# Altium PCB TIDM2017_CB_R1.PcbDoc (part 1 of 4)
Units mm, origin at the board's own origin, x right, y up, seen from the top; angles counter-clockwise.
Board outline 120 x 77 mm, 4 copper layers (Top Layer, Layer 1, Layer 2, Bottom Layer), stack 1.856 mm thick; 246 components, 167 nets, 1255 pads, 326 vias.
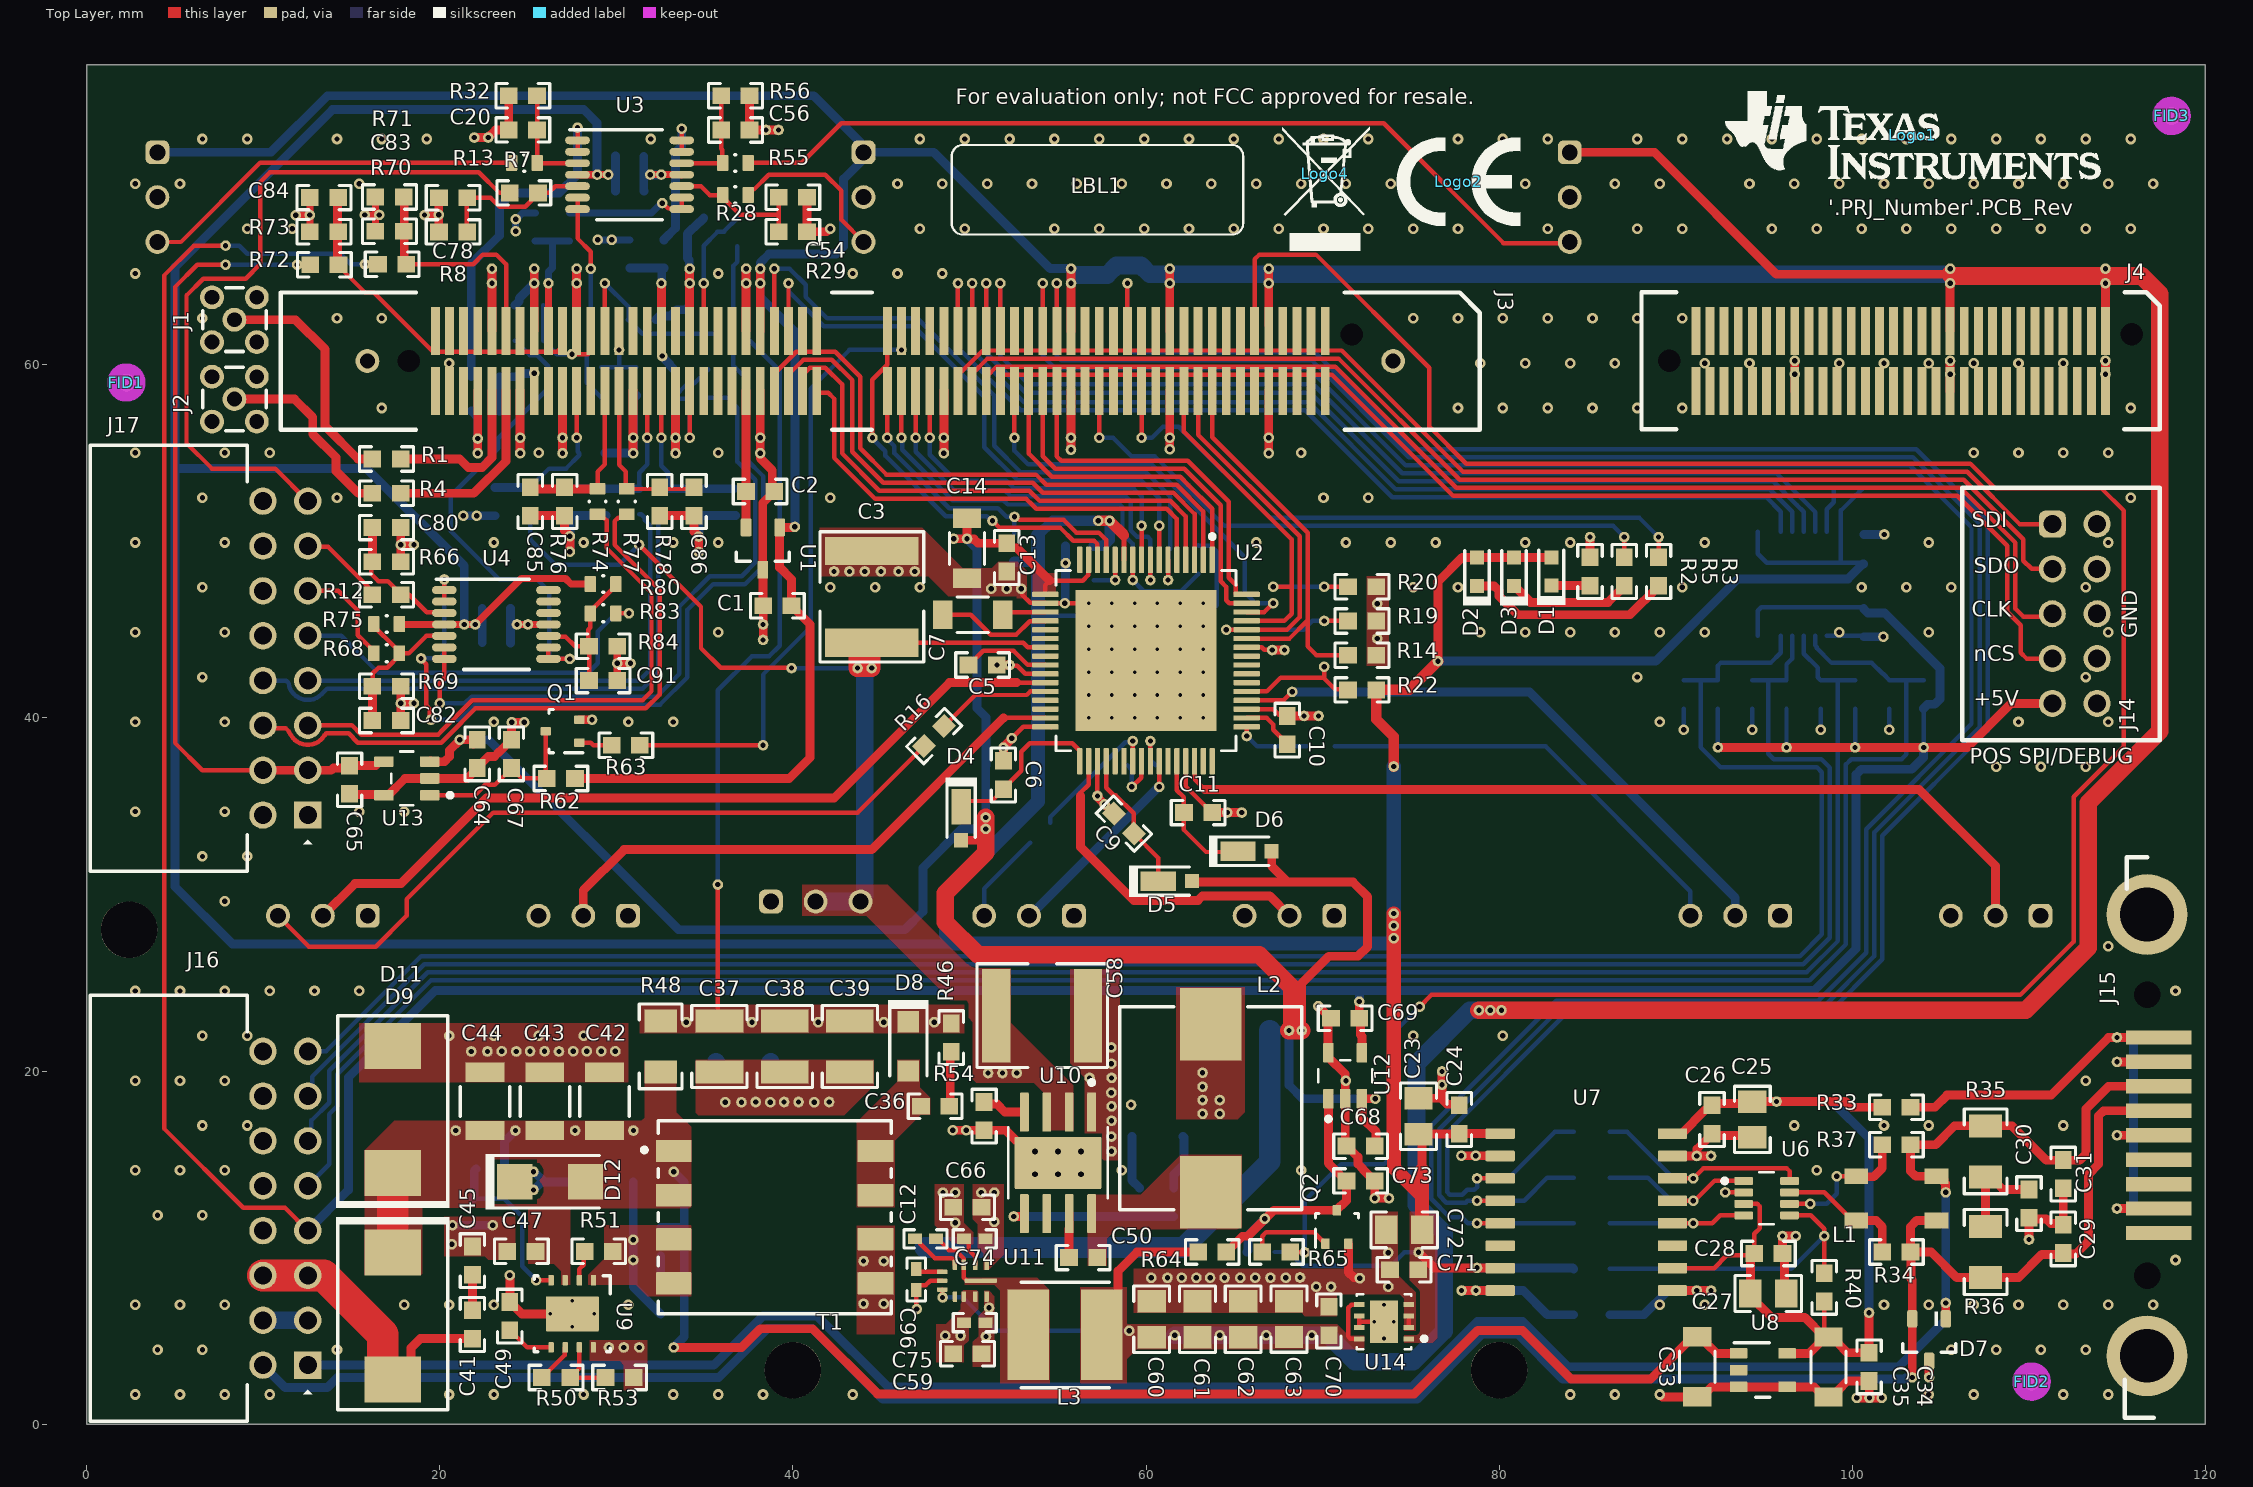
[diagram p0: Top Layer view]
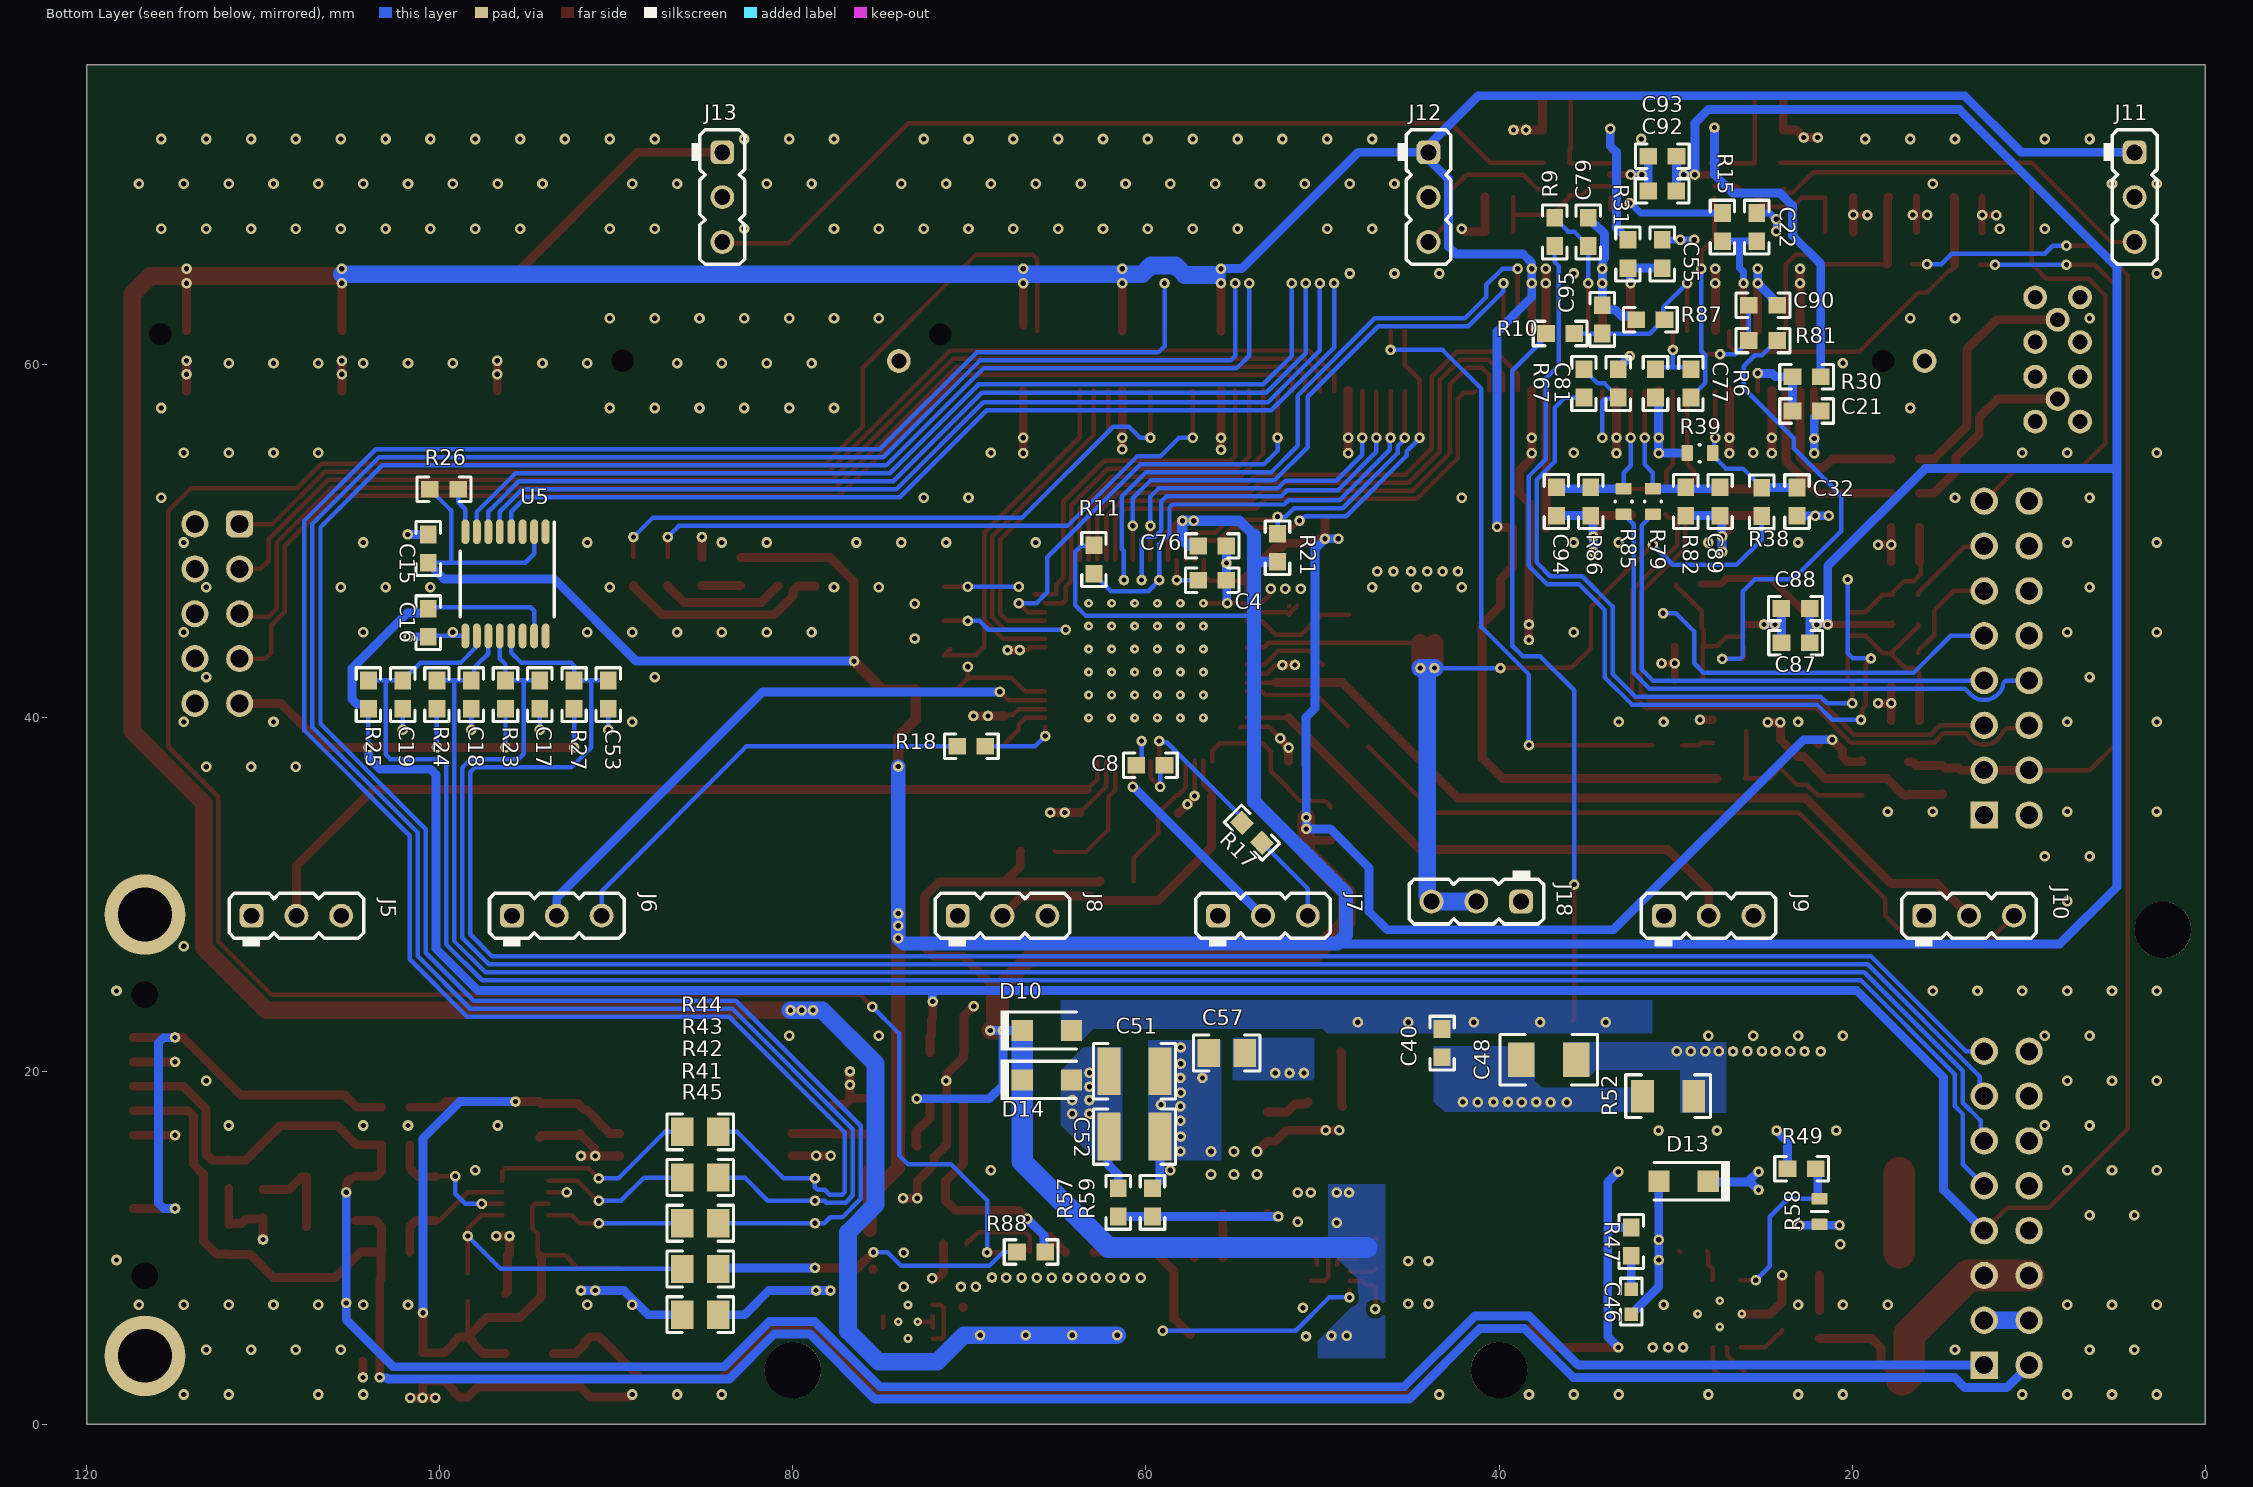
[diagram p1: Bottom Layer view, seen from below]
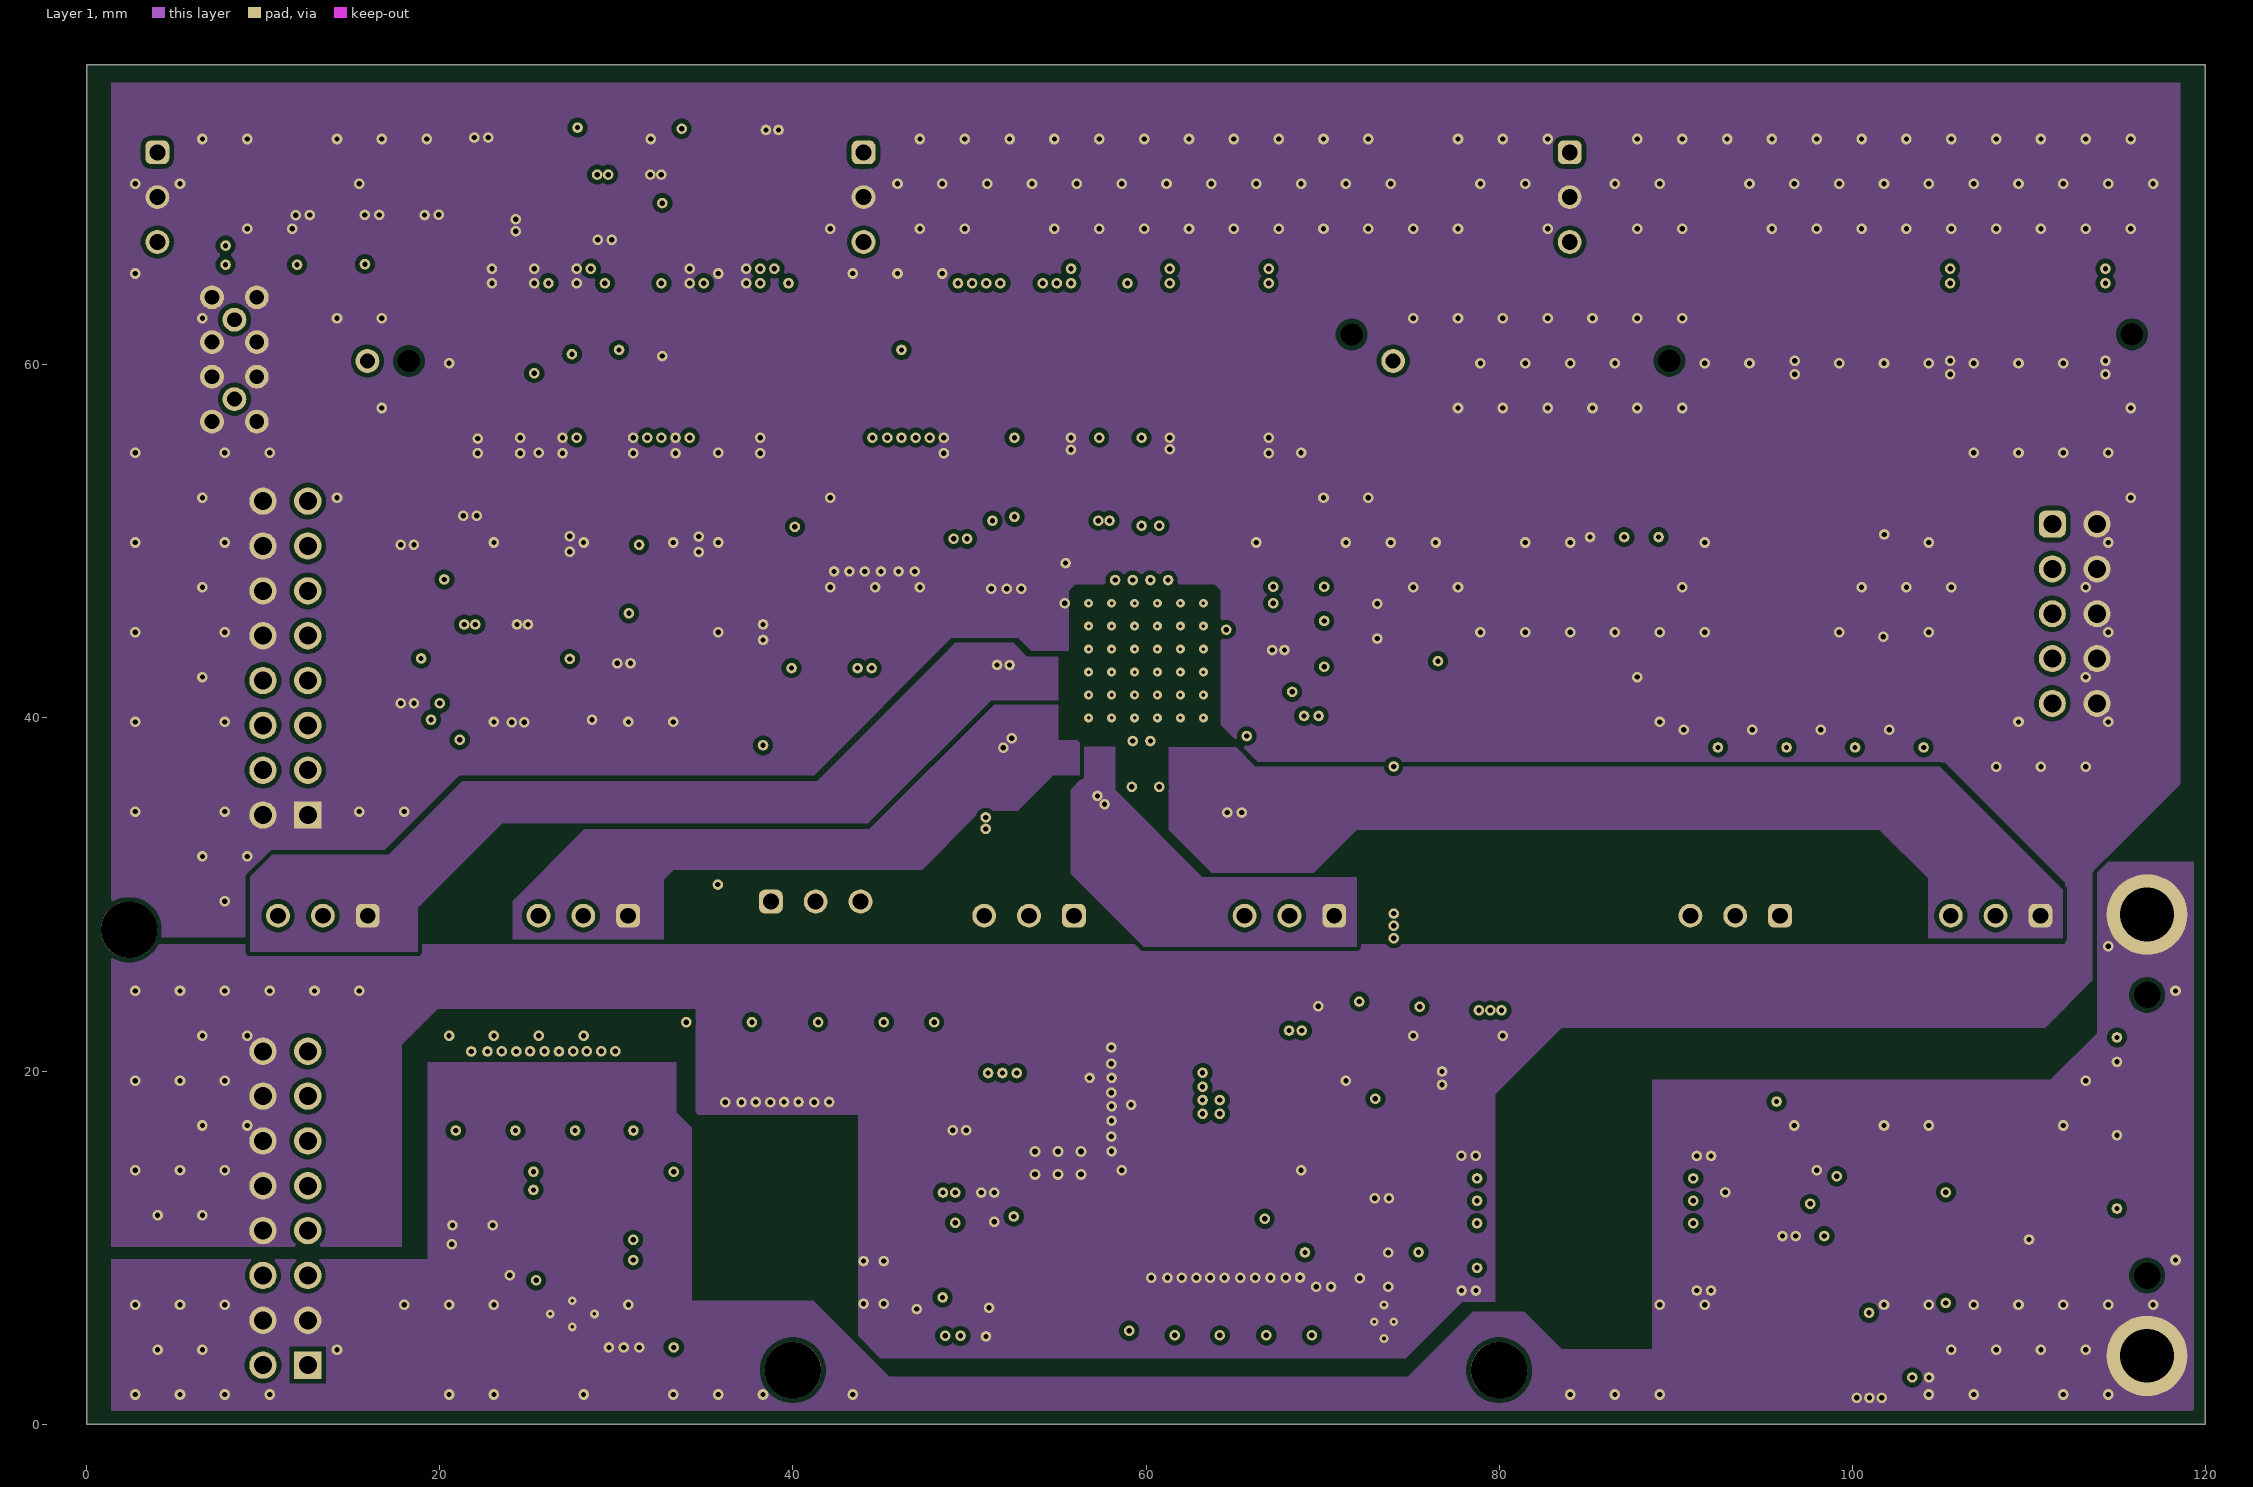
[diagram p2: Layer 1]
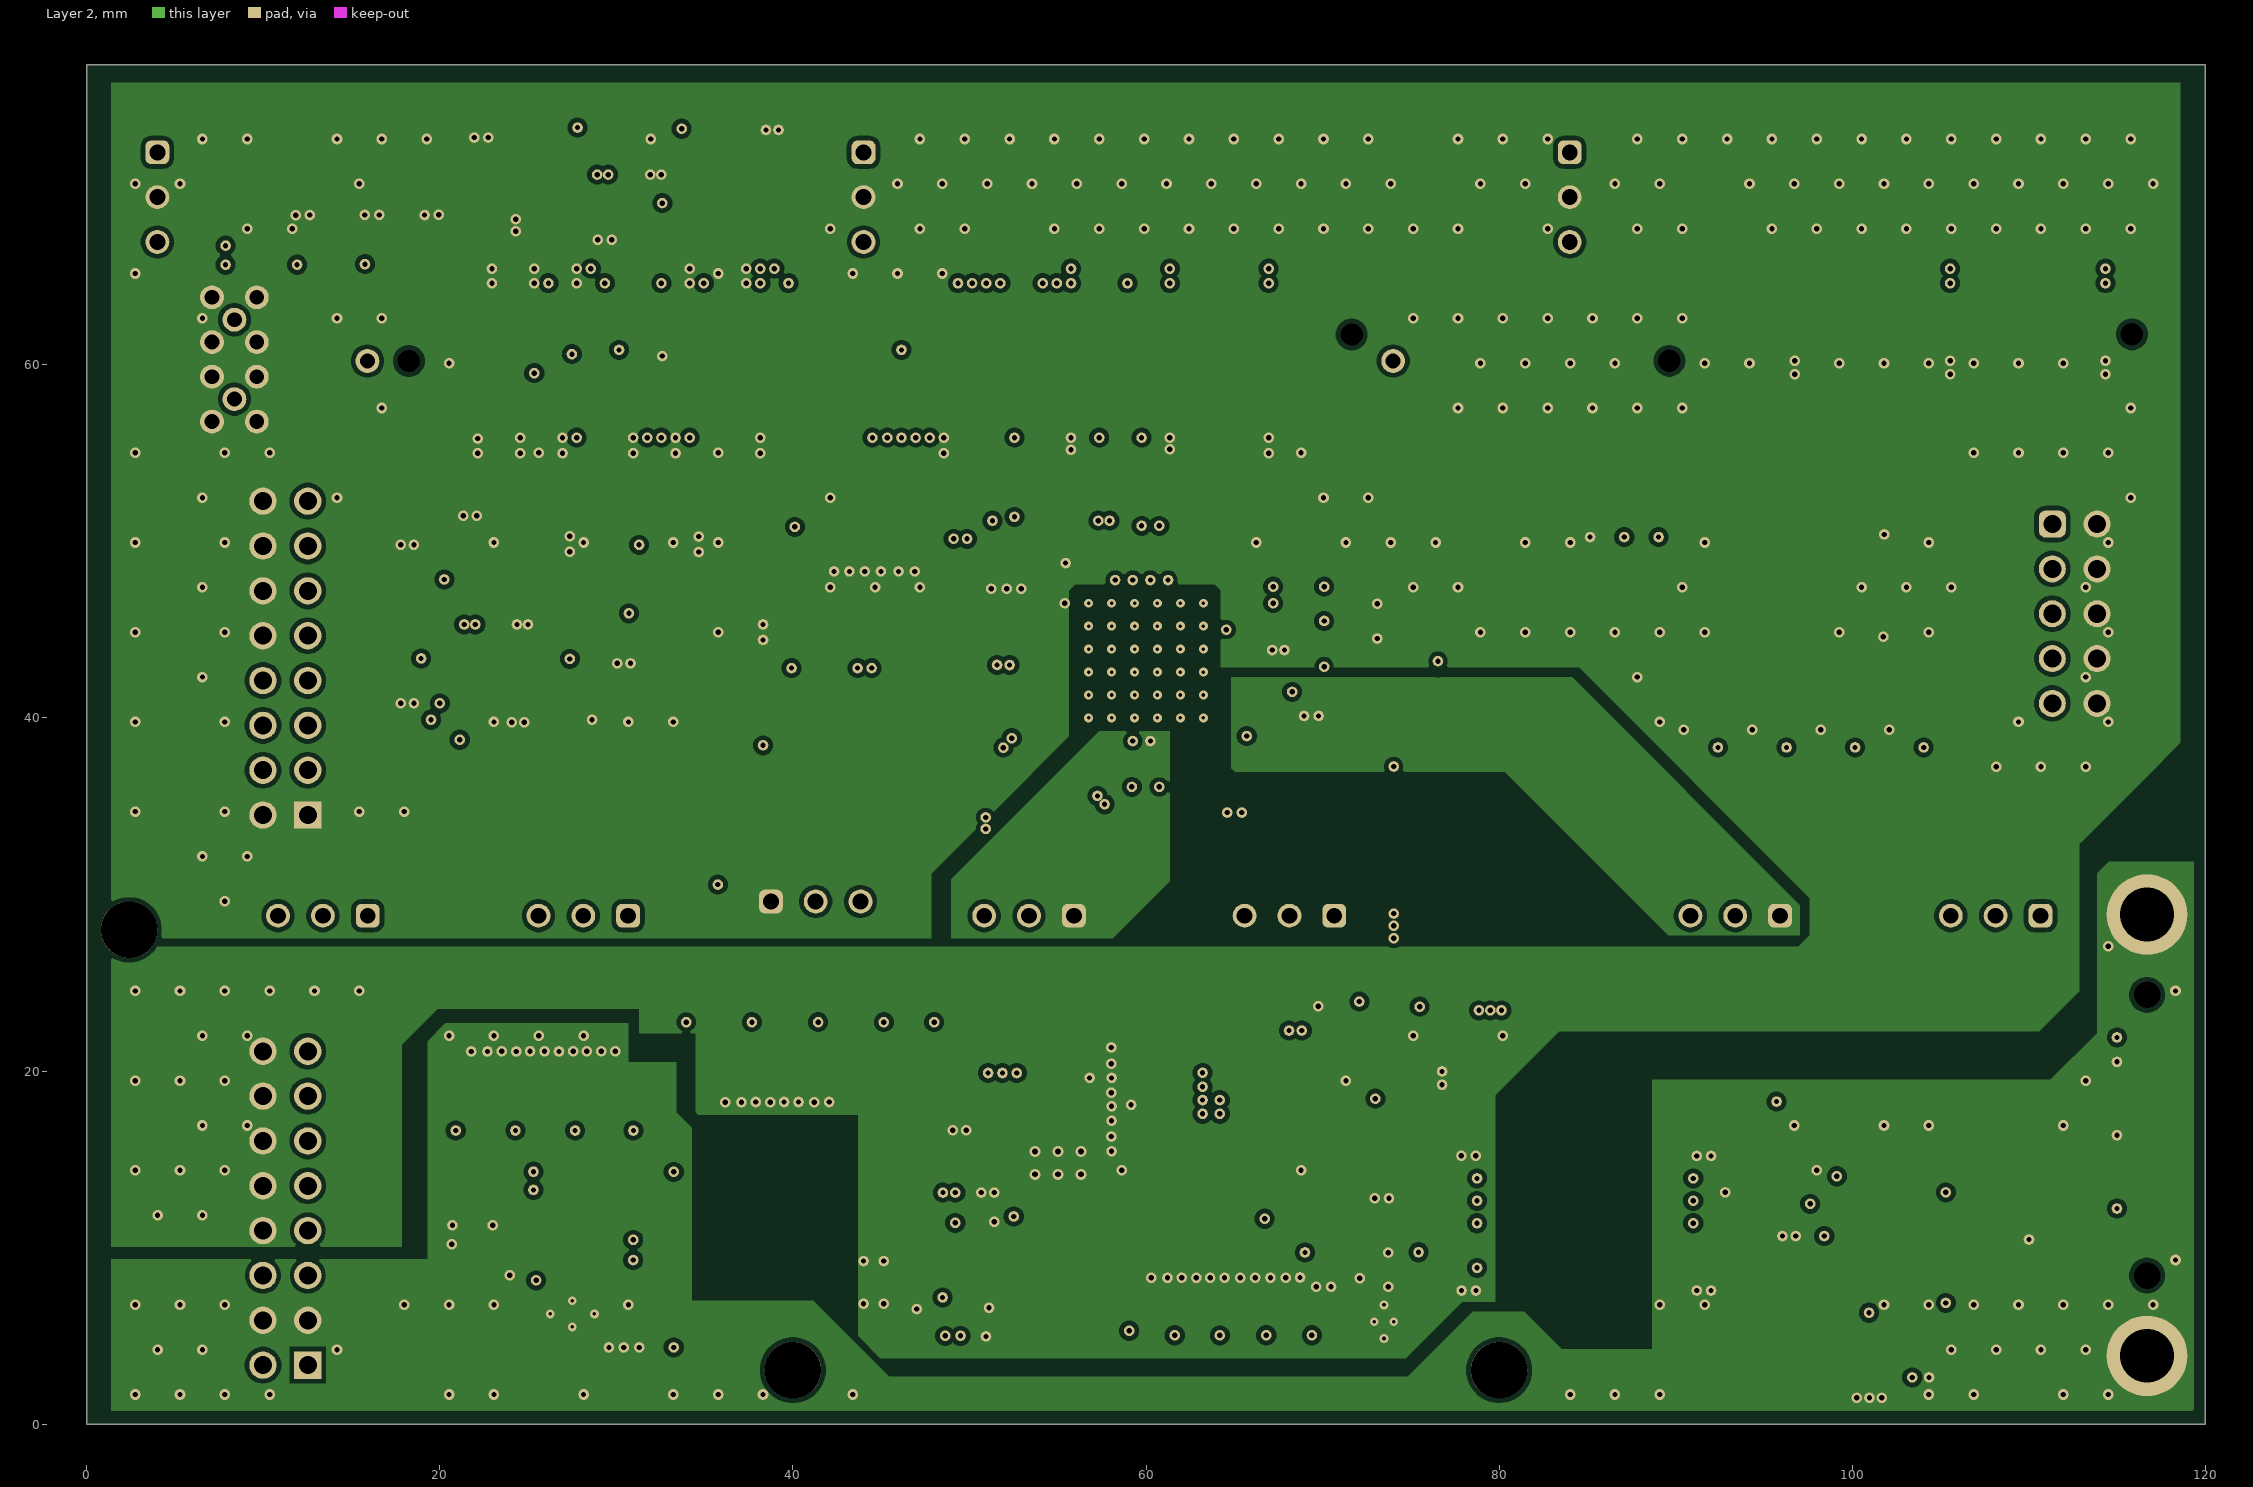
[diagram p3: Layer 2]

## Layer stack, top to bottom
Top Solder: solder mask 0.0102, Solder Resist, Dk 3.5
Top Layer: signal copper 0.07
Dielectric 1: prepreg 0.0711, PP-006, Dk 4.1
Layer 1: signal copper 0.035
Dielectric1: core 1.5037, FR-4 High Tg, Dk 4.8
Layer 2: signal copper 0.035
Dielectric 2: prepreg 0.0711, PP-006, Dk 4.1
Bottom Layer: signal copper 0.07
Bottom Solder: solder mask 0.0102, Solder Resist, Dk 3.5

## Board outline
0,0 0,77 120,77 120,0

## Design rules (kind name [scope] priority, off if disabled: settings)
AcuteAngle [All] p1: minimum=4.50000000000000E+0001 checktracksonly=FALSE
AssemblyTestPointUsage [All] p1: valid=2
BoardOutlineClearance BoardOutlineClearance_MountingHoles [OnCopper and InComponentClass('Mounting Holes')] p1: gap=1 ignorepadtopadclearanceinfootprint=FALSE
BoardOutlineClearance BoardOutlineClearance_Poly [OnCopper and IsPoly] p2: gap=0.635 ignorepadtopadclearanceinfootprint=FALSE
BoardOutlineClearance [OnCopper and Not InComponentClass('Logo') and not InComponentClass('FiducialMark') and not InRegion(1000,500,4000,800) and not InPoly] p3: gap=1.016 ignorepadtopadclearanceinfootprint=FALSE
Clearance Clearance_Keepouts [((IsTrack Or IsArc) And Not InPoly) And IsFree and IsKeepOut vs ((IsTrack Or IsArc) And Not InPoly) And IsFree and IsKeepOut] p1: gap=0 ignorepadtopadclearanceinfootprint=FALSE
Clearance Clearance_Poly [InPolygon] p2: gap=0.254 ignorepadtopadclearanceinfootprint=TRUE
Clearance Clearance_FiducialMark [IsKeepOut and InComponentClass('FiducialMark') vs IsPad and InComponentClass('FiducialMark')] p3: gap=0 ignorepadtopadclearanceinfootprint=FALSE
Clearance [All] p4: gap=0.2 ignorepadtopadclearanceinfootprint=TRUE
ComponentClearance ComponentClearance_MountingHoles_FiducialMarks [InComponentClass('Mounting Holes') vs InComponentClass('FiducialMark')] p1: gap=1.27 collisioncheckmode=3 verticalgap=0.254 showdistances=FALSE
ComponentClearance ComponentClearance_Shunt [InComponentClass('Header') vs InComponentClass('Shunt')] p2: gap=0 collisioncheckmode=3 verticalgap=0 showdistances=FALSE
ComponentClearance ComponentClearance_Logo [InComponentClass('Logo')] p3: gap=0.762 collisioncheckmode=3 verticalgap=0.254 showdistances=FALSE
ComponentClearance ComponentClearance_ScrewToNut [(HasFootprint('NY PMS 440 0025 PH')) vs (HasFootprint('Keystone_1902C'))] p4: gap=0.127 collisioncheckmode=3 verticalgap=0.254 showdistances=FALSE
ComponentClearance ComponentClearance_MountingHoles [InComponentClass('Mounting Holes')] p5: gap=2.54 collisioncheckmode=3 verticalgap=2540 showdistances=FALSE
ComponentClearance ComponentClearance_SmallPassives [HasFootprint('0201*') or HasFootprint('0402*') or HasFootprint('0508') or HasFootprint('0603*') or HasFootprint('0612') or HasFootprint('0805*') or HasFootprint('0815*') or HasFootprint('0830*') or HasFootprint('1206*') or HasFootprint('1210*') or HasFootprint('1808*') or HasFootprint('1812*') or HasFootprint('1825*') or HasFootprint('2010*') or HasFootprint('2220*') or HasFootprint('2225*') or HasFootprint('2512*') or HasFootprint('2728*') or HasFootprint('3518*') vs HasFootprint('0201*') or HasFootprint('0402*') or HasFootprint('0508') or HasFootprint('0603*') or HasFootprint('0612') or HasFootprint('0805*') or HasFootprint('0815*') or HasFootprint('0830*') or HasFootprint('1206*') or HasFootprint('1210*') or HasFootprint('1808*') or HasFootprint('1812*') or HasFootprint('1825*') or HasFootprint('2010*') or HasFootprint('2220*') or HasFootprint('2225*') or HasFootprint('2512*') or HasFootprint('2728*') or HasFootprint('3518*')] p6: gap=0.38 collisioncheckmode=3 verticalgap=0.254 showdistances=FALSE
ComponentClearance ComponentClearance_THtoSMT [IsThruComponent vs IsSMTComponent] p7: gap=0.762 collisioncheckmode=3 verticalgap=0.762 showdistances=FALSE
ComponentClearance ComponentClearance_THtoTH [IsThruComponent vs IsThruComponent] p8: gap=0.508 collisioncheckmode=3 verticalgap=0.762 showdistances=FALSE
ComponentClearance [All] p9: gap=0.508 collisioncheckmode=3 verticalgap=0.254 showdistances=FALSE
DiffPairsRouting [All] p1: maxlimit=2.54 minlimit=0.254 mostfreqgap=0.254 toplayer_minwidth=0.381 toplayer_maxwidth=0.381 toplayer_prefwidth=0.381 midlayer1_minwidth=0.381 midlayer1_maxwidth=0.381 midlayer1_prefwidth=0.381 midlayer2_minwidth=0.381 midlayer2_maxwidth=0.381 midlayer2_prefwidth=0.381 bottomlayer_minwidth=0.381 bottomlayer_maxwidth=0.381 bottomlayer_prefwidth=0.381 maxuncoupledlength=25.4
FabricationTestPointUsage TestPointUsage [All] p1: valid=2 allowmultiple=FALSE
FabricationTestpoint Testpoint [All] p1: side=3 testpointundercomponent=TRUE minsize=1.016 maxsize=2.54 preferedsize=1.524 minholesize=0 maxholesize=1.016 preferedholesize=0.813 testpointgrid=0.025 allowsidetop=TRUE allowsidebottom=TRUE usegrid=TRUE gridtolerance=0
FanoutControl Fanout_LCC [IsLCC] p1: bgadir=Out bgaviamode=Centered fanoutstyle=Auto fanoutdirection=Alternating viagrid=0.025 // Fanout_LCC (Default Rule)
FanoutControl Fanout_BGA [IsBGA] p2: bgadir=Out bgaviamode=Centered fanoutstyle=Auto fanoutdirection=Alternating viagrid=0.025 // Fanout_BGA (Default Rule)
FanoutControl Fanout_Default [All] p4: bgadir=Out bgaviamode=Centered fanoutstyle=Auto fanoutdirection=Alternating viagrid=0.025 // Fanout_Default (Default Rule)
FanoutControl Fanout_Small [(CompPinCount < 5)] p5: bgadir=Out bgaviamode=Centered fanoutstyle=Auto fanoutdirection=OutThenIn viagrid=0.025 // Fanout_Small (Default Rule)
HoleSize [All] p1: absolutevalues=TRUE maxlimit=6.375 minlimit=0.2 maxpercent=80.000 minpercent=20.000
MinimumAnnularRing MinimumAnnularRing_ThermalPadVias [IsVia and InAnyComponent] p1: minimumring=0.15
MinimumAnnularRing [All] p2: minimumring=0.2
MinimumSolderMaskSliver MinimumSolderMaskSliver_Logo [InComponentClass('Logo') vs InComponentClass('Logo')] p1: minsoldermaskwidth=0.018
MinimumSolderMaskSliver [All] p2: minsoldermaskwidth=0.1
PlaneConnect [All] p1: planeconnectstyle=Relief reliefexpansion=0.254 reliefentries=4 reliefconductorwidth=0.254 reliefairgap=0.254
PolygonConnect [All] p1: connectstyle=Direct reliefconductorwidth=0.254 reliefentries=4 polygonreliefangle="90 Angle" airgapwidth=0.254
RoutingLayers [All] p1: top layer_v5=TRUE mid layer 1_v5=FALSE mid layer 2_v5=FALSE bottom layer_v5=TRUE
RoutingVias ThermalPadVias [IsVia and InAnyComponent] p1: holewidth=0.2 width=0.5 viastyle="Through Hole" minholewidth=0.2 minwidth=0.5 maxholewidth=0.33 maxwidth=0.6
RoutingVias [All] p2: holewidth=0.406 width=0.864 viastyle="Through Hole" minholewidth=0.2 minwidth=0.61 maxholewidth=1.016 maxwidth=1.651
SilkToBoardRegionClearance [Not ((IsComment or IsDesignator) And (Hide <> 'False')) and not InRegion(1000,500,4000,800)] p1:
SilkToSilkClearance SilkToSilkClearance_Pb-FreeLogo [(HasFootprint('Pb-Free_Overlay_Medium') OR HasFootprint('Pb-Free_Overlay_Small')) vs (HasFootprint('Pb-Free_Overlay_Medium') OR HasFootprint('Pb-Free_Overlay_Small'))] p1: silktosilkclearance=0
SilkToSilkClearance [All] p2: silktosilkclearance=0.1
SilkToSolderMaskClearance SilkToComponentPadClearance [(IsPad or IsFill or IsRegion) and InAnycomponent] p1: minsilkscreentomaskgap=0.127 clearancetoexposedcopper=TRUE
SilkToSolderMaskClearance "Silk to Solder Mask Opening" [All] p2: minsilkscreentomaskgap=0.1 clearancetoexposedcopper=FALSE
SolderMaskExpansion [All] p1: expansion=0.05 istentingtop=FALSE
UnRoutedNet [All] p1: checkbadconnections=TRUE
Width [All] p1: maxlimit=2.54 minlimit=0.152 preferedwidth=0.254 checkconnectedcopper=TRUE
13 further rules are at their usual default settings.

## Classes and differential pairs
component class Header: J14
component class TIDM2017_CB_R1: J16 J17
component class Logo: Logo1
component class Label: LBL1
component class FiducialMark: FID1 FID2 FID3
component class AssemblyNote: ZZ1 ZZ2 ZZ3 ZZ4
component class Designator: C15 C16 C17 C18 C19 C53 R23 R24 R25 R26 R27 U5
component class Designator: C20 C21 C22 C54 C55 C56 C77 C78 C79 C80 C81 C82 C83 C84 C85 C86 C87 C88 C89 C90 C91 C92 C93 C94 C95 J11 J12 J13 R6 R7 R8 R9 R10 R12 R13 R15 R28 R29 R30 R31 R32 R55 R56 R66 R67 R68 R69 R70 R71 R72 R73 R74 R75 R76 R77 R78 R79 R80 R81 R82 R83 R84 R85 R86 R87 U3 U4
component class Designator: C3 C4 C5 C6 C7 C8 C9 C10 C11 C13 C14 C32 C76 D4 D5 D6 J5 J6 J7 J8 J9 J10 J18 R14 R16 R17 R18 R19 R20 R21 R22 R38 R39 U2
component class C2000_Control_Card: C1 C2 D1 D2 D3 J1 J2 J3 J4 J14 R1 R2 R3 R4 R5 R11 U1

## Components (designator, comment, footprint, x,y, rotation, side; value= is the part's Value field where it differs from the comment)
C1 "CGA3E2X7R1H104K080AA" 0603 39.122,46.351 r180 top value=0.1uF
C2 "CGA3E2X7R1H104K080AA" 0603 38.141,52.829 r180 top value=0.1uF
C3 "CGA9N2X7R2A475M230KA" 2220_250 44.469,46.854 r270 top value=4.7uF
C4 "CGA3E3X7R1H474M080AE" 0603 56.246,47.802 r180 bottom value=0.47uF
C5 "GRT188C81E475KE13D" 0603 50.75,43 r180 top value=4.7uF
C6 "GRT188C81E475KE13D" 0603 51.922,36.767 r270 top value=4.7uF
C7 "CGA5L2X7R2A474K160AA" 1206_180 50.182,45.839 r0 top value=0.47uF
C8 "GRT188C81E475KE13D" 0603 59.75,37.321 r180 bottom value=4.7uF
C9 "GRT188C81E475KE13D" 0603 58.75,34.016 r315 top value=4.7uF
C10 "GRT188C81E475KE13D" 0603 68.004,39.311 r270 top value=4.7uF
C11 "GRT188C81E475KE13D" 0603 62.95,34.642 r180 top value=4.7uF
C12 "CGA2B3X7R1H104M050BB" 0402 47.512,10.489 r180 top value=0.1uF
C13 "CGA3E3X8R1H104K080AE" 0603 52.106,49.092 r270 top value=0.1uF
C14 "CGA5L1X7R1H106K160AC" 1206_190 49.859,49.604 r270 top value=10uF
C15 "CGA3E2X7R1H104K080AA" 0603 100.657,49.595 r90 bottom value=0.1uF
C16 "CGA3E2X7R1H104K080AA" 0603 100.657,45.395 r90 bottom value=0.1uF
C17 "GRM1885C1H102JA01D" 0603 94.339,41.322 r270 bottom value=1000pF
C18 "GRM1885C1H102JA01D" 0603 98.222,41.322 r270 bottom value=1000pF
C19 "GRM1885C1H102JA01D" 0603 102.105,41.322 r270 bottom value=1000pF
C20 "GCM1885C1H471JA16D" 0603 24.703,73.305 r0 top value=470pF
C21 "GRM1885C1H471JA01D" 0603 22.58,57.385 r180 bottom value=470pF
C22 "GRM1885C1H471JA01D" 0603 25.405,67.804 r90 bottom value=470pF
C23 "CGA4J1X7S1C106K125AC" 0805_HV 75.432,17.444 r90 top locked value=10uF
C24 "0603YC104K4T4A" 0603 77.75,17.255 r90 top locked value=0.1uF
C25 "CGA4J1X7S1C106K125AC" 0805_HV 94.344,17.255 r270 top value=10uF
C26 "0603YC104K4T4A" 0603 92.059,17.255 r270 top value=0.1uF
C27 "CGA4J1X7S1C106K125AC" 0805_HV 95.252,7.4 r0 top value=10uF
C28 "0603YC104K4T4A" 0603 95.252,9.665 r0 top value=0.1uF
C29 "GRM1885C2A680JA01D" 0603 111.958,10.492 r90 top value=68pF
C30 "GCM188R71H472KA37D" 0603 110.016,12.488 r90 top value=4700pF
C31 "GRM1885C2A680JA01D" 0603 111.958,14.161 r90 top value=68pF
C32 "CGA3E3X8R1H104K080AE" 0603 23.125,52.25 r90 bottom value=0.1uF
C33 "CGA5L1X7R1H106K160AC" 1206_190 91.224,3.245 r270 top value=10uF
C34 "CGA3E3X8R1H104K080AE" 0603 100.955,3.245 r270 top value=0.1uF
C35 "CGA5L1X7R1H106K160AC" 1206_190 98.66,3.236 r270 top value=10uF
C36 "GRM1885C2A220JA01D" 0603 48.053,18 r180 top locked value=22pF
C37 "TMK325B7226KMHP" 1210_270 35.841,21.394 r270 top locked value=22uF
C38 "TMK325B7226KMHP" 1210_270 39.535,21.394 r270 top locked value=22uF
C39 "TMK325B7226KMHP" 1210_270 43.228,21.394 r270 top locked value=22uF
C40 "C0603C104K5RACAUTO" 0603 43.228,21.584 r270 bottom value=0.1uF
C41 "CGA3E2X7R1H473K080AA" 0603 21.847,5.644 r90 top locked value=0.047uF
C42 "CGA6P3X7S1H106K250AB" 1210_280 29.326,18.281 r270 top locked value=10uF
C43 "CGA6P3X7S1H106K250AB" 1210_280 25.946,18.281 r270 top locked value=10uF
C44 "CGA6P3X7S1H106K250AB" 1210_280 22.566,18.281 r270 top locked value=10uF
C45 "CGA3E2X7R1H473K080AA" 0603 21.847,9.261 r90 top locked value=0.047uF
C46 "GRM1885C2A220JA01D" 0603_HV 32.511,6.939 r270 bottom value=22pF
C47 "C0603C104K5RACTU" 0603 24.619,9.786 r180 top locked value=0.1uF
C48 "202R18W102KV4E" 1206_190M 37.191,20.643 r180 bottom value=1000pF
C49 "GCM188R71E473KA37D" 0603 23.966,6.119 r90 top locked value=0.047uF
C50 "C0603C104K5RACAUTO" 0603 56.436,9.434 r0 top locked value=0.1uF
C51 "TMK325B7226KMHP" 1210_270 60.65,19.984 r180 bottom locked value=22uF
C52 "TMK325B7226KMHP" 1210_270 60.65,16.29 r180 bottom value=22uF
C53 "GRM1885C1H102JA01D" 0603 90.456,41.322 r270 bottom value=1000pF
C54 "GCM1885C1H471JA16D" 0603 39.997,69.5 r180 top value=470pF
C55 "GRM1885C1H471JA01D" 0603 30.76,66.281 r90 bottom value=470pF
C56 "GCM1885C1H471JA16D" 0603 36.744,73.305 r180 top value=470pF
C57 "GCM21BR72A104KA37L" 0805_HV 55.425,21.019 r0 bottom locked value=0.1uF
C58 "CGA9N2X7R2A475M230KA" 2220_250 54.119,23.135 r0 top locked value=4.7uF
C59 "GRT188C81C106ME13D" 0603 49.886,3.982 r0 top value=10uF
C60 "GRT21BR61E226ME13L" 0805_HV 60.324,5.939 r90 top locked value=22uF
C61 "GRT21BR61E226ME13L" 0805_HV 62.914,5.939 r90 top locked value=22uF
C62 "GRT21BR61E226ME13L" 0805_HV 65.504,5.939 r90 top locked value=22uF
C63 "GRT21BR61E226ME13L" 0805_HV 68.094,5.949 r90 top locked value=22uF
C64 "GCM188R71C105KA64J" 0603 22.115,37.967 r270 top value=1uF
C65 "GRM188R71A225KE15J" 0603 14.887,36.5 r270 top value=2.2uF
C66 "GRT188C81C106ME13D" 0603 49.886,12.283 r0 top value=10uF
C67 "C0603C104K5RACAUTO" 0603 24.056,37.967 r270 top value=0.1uF
C68 "GCM188R71C105KA64J" 0603 72.157,15.747 r180 top locked value=1uF
C69 "GRM188R71A225KE15J" 0603 71.282,22.985 r180 top locked value=2.2uF
C70 "GRM188R71A225KE15J" 0603 70.361,5.84 r90 top locked value=2.2uF
C71 "GRM188R71A225KE15J" 0603 74.624,8.744 r180 top locked value=2.2uF
C72 "GRT21BR61E226ME13L" 0805_HV 74.624,11.008 r180 top locked value=22uF
C73 "C0603C104K5RACAUTO" 0603 72.157,13.777 r180 top locked value=0.1uF
C74 "GCM155R71C224KE02D" 0402 50.299,10.489 r0 top value=0.22uF
C75 "GCM155R71C224KE02D" 0402 50.299,5.754 r0 top value=0.22uF
C76 "CGA3E3X8R1H104K080AE" 0603 56.246,49.744 r180 bottom value=0.1uF
C77 "GRM1885C1H471JA01D" 0603 31.139,58.948 r270 bottom value=470pF
C78 "GCM1885C1H471JA16D" 0603 20.752,69.472 r0 top value=470pF
C79 "GRM1885C1H471JA01D" 0603 34.95,67.53 r90 bottom value=470pF
C80 "GCM1885C1H471JA16D" 0603 16.982,50.785 r180 top value=470pF
C81 "GRM1885C1H471JA01D" 0603 33.253,58.948 r90 bottom value=470pF
C82 "GCM1885C1H471JA16D" 0603 16.982,39.858 r180 top value=470pF
C83 "GCM1885C1H471JA16D" 0603 17.147,67.568 r0 top value=470pF
C84 "GCM1885C1H471JA16D" 0603 13.438,69.476 r0 top value=470pF
C85 "GCM1885C1H471JA16D" 0603 25.128,52.26 r90 top value=470pF
C86 "GCM1885C1H471JA16D" 0603 34.397,52.26 r90 top value=470pF
C87 "GRT188C81E475KE13D" 0603 23.205,44.254 r180 bottom value=4.7uF
C88 "CGA3E3X8R1H104K080AE" 0603 23.21,46.197 r0 bottom value=0.1uF
C89 "GCM1885C1H471JA16D" 0603 27.481,52.26 r90 bottom value=470pF
C90 "GRM1885C1H471JA01D" 0603 25.053,63.375 r180 bottom value=470pF
C91 "GCM1885C1H471JA16D" 0603 29.25,42.12 r180 top value=470pF
C92 "GRT188C81E475KE13D" 0603 30.76,69.854 r180 bottom value=4.7uF
C93 "CGA3E3X8R1H104K080AE" 0603 30.749,71.823 r0 bottom value=0.1uF
C94 "GCM1885C1H471JA16D" 0603 36.75,52.26 r90 bottom value=470pF
C95 "GCM1885C1H471JA16D" 0603 34.15,62.575 r270 bottom locked value=470pF
C96 "GRT155R6YA105KE13D" 0402 46.984,8.188 r270 top value=1uF
D1 "150060GS75000" WL-SMCW_GREEN 82.959,48.295 r90 top value=Green
D2 "150060RS75000" WL-SMCW_RED 78.742,48.281 r90 top value=Red
D3 "150060GS75000" WL-SMCW_GREEN 80.851,48.281 r90 top value=Green
D4 "PD3S220L-7" PowerDI323 49.527,34.321 r270 top value=20V
D5 "PD3S220L-7" PowerDI323 61.349,30.76 r0 top value=20V
D6 "PD3S220L-7" PowerDI323 65.857,32.45 r0 top value=20V
D7 "CDSOT23-SM712" SOT-23 104.355,4.764 r270 top value=7V
D8 "PMEG60T30ELRX" SOD-123W 46.537,21.394 r270 top value=60V
D9 "SS3H10HE3_A/I" SMC_265 17.332,6.119 r270 top locked value=100V
D10 "PMEG60T30ELRX" SOD-123W 65.614,22.294 r180 bottom locked value=60V
D11 "TPSMD26A" SMC_265 17.332,17.828 r90 top locked value=26V
D12 "3SMAJ5935B-TP" SMA 26.25,13.723 r0 top locked value=27V
D13 "PMEG60T30ELRX" SOD-123W 29.55,13.758 r0 bottom value=60V
D14 "PMEG60T30ELRX" SOD-123W 65.614,19.5 r180 bottom value=60V
FID1 "Fiducial" Fiducial10-20 2.25,59 r0 top
FID2 "Fiducial" Fiducial10-20 110.161,2.411 r0 top
FID3 "Fiducial" Fiducial10-20 118.094,74.1 r0 top
J1 "0734151471" Molex_0734151471 8.364,62.557 r0 top
J2 "0734151471" Molex_0734151471 8.364,58.058 r0 top
J3 "HSEC8-160-01-L-DV-A-BL" controlCARD-120HSEC 43.107,60.197 r0 top locked
J4 "HSEC8-130-01-L-DV-A" controlCARD-180HSEC-60pinAddon 102.748,60.228 r0 top locked
J5 "801-41-003-10-001000" Mill-Max_801-41-003-10-001000 108.126,28.798 r180 bottom locked
J6 "801-41-003-10-001000" Mill-Max_801-41-003-10-001000 93.376,28.798 r180 bottom locked
J7 "801-41-003-10-001000" Mill-Max_801-41-003-10-001000 53.376,28.798 r180 bottom locked
J8 "801-41-003-10-001000" Mill-Max_801-41-003-10-001000 68.126,28.798 r180 bottom locked
J9 "801-41-003-10-001000" Mill-Max_801-41-003-10-001000 28.126,28.798 r180 bottom locked
J10 "801-41-003-10-001000" Mill-Max_801-41-003-10-001000 13.376,28.798 r180 bottom locked
J11 "801-41-003-10-001000" Mill-Max_801-41-003-10-001000 4,69.5 r270 bottom locked
J12 "801-41-003-10-001000" Mill-Max_801-41-003-10-001000 44,69.5 r270 bottom locked
J13 "801-41-003-10-001000" Mill-Max_801-41-003-10-001000 84,69.5 r270 bottom locked
J14 "TSW-105-08-G-D" Samtec_TSW-105-08-x-D 112.605,45.903 r0 top
J15 "190-009-263R001" NORCOMP_190-009-263R001 119.5,16.365 r270 top locked
J16 "TSS-108-04-L-D-RA" Samtec_TSS-108-04-x-D-RA 11.25,12.23 r180 top locked
J17 "TSS-108-04-L-D-RA" Samtec_TSS-108-04-x-D-RA 11.25,43.39 r180 top locked
J18 "801-41-003-10-001000" Mill-Max_801-41-003-10-001000 41.29,29.599 r0 bottom locked
L1 "ACT45B-510-2P-TL003" ACT45B_NoSilk 102.505,12.79 r180 top value=51uH
L2 "PA4342.683NLT" PA4342_2 63.673,17.89 r180 top locked value=68uH
L3 "SRN6045TA-100M" SRN6045TA 55.411,5.062 r0 top locked value=10uH
LBL1 "THT-14-423-10" Label_650x200 57.25,69.918 r0 top
Logo1 "Texas Instruments" TI_Stacked_Overlay_Small 103.442,73.01 r0 top
Logo2 "CE Mark" CE_Mark_5mm 77.705,70.372 r0 top
Logo3 "FCC disclaimer" FCC_disclaimer 58.25,89.223 r0 top
Logo4 "WEEE logo" WEEE_Minimum 70.15,70.826 r0 top
Q1 "BSS138WH6327XTSA1" SOT-323 26.95,39.25 r180 top locked value=60V
Q2 "BSS138WH6327XTSA1" SOT-323 70.811,11.164 r90 top locked value=60V
R1 "CRCW060347R0FKEA" 0603 16.982,54.667 r0 top value=47.0
R2 "CRCW06034K64FKEA" 0603 85.15,48.295 r270 top value=4.64k
R3 "CRCW06031K15FKEA" 0603 89.035,48.295 r270 top value=1.15k
R4 "CRCW060347R0FKEA" 0603 16.982,52.725 r0 top value=47.0
R5 "CRCW06034K64FKEA" 0603 87.091,48.295 r270 top value=4.64k
R6 "RC0603FR-0751R1L" 0603 29.13,58.948 r90 bottom value=51.1
R7 "RT0603BRD0718K4L" 0603 24.762,69.74 r0 top value=18.4k
R8 "RC0603FR-0710KL" 0603 20.752,67.53 r0 top value=10.0k
R9 "RC0603FR-0751R1L" 0603 36.844,67.53 r90 bottom value=51.1
R10 "RT0603DRE0743K7L" 0603 36.544,61.775 r180 bottom locked value=43.7k
R11 "CRCW060310K0FKEA" 0603 62.95,48.973 r90 bottom value=10.0k
R12 "RT0603BRD0718K4L" 0603 16.982,46.979 r0 top value=18.4k
R13 "ERJ-PB3B6041V" FP-ERJ-PB3B6041V_0603-MFG 24.787,71.44 r0 top
R14 "ERA-3ARW104V" 0603 72.239,43.551 r180 top value=100k
R15 "RC0603FR-0751R1L" 0603 27.349,67.804 r270 bottom value=51.1
R16 "RT0603BRD07271RL" 0603 48,38.975 r225 top value=271
R17 "RT0603BRD07271RL" 0603 54,33.5 r225 bottom value=271
R18 "RT0603BRD07271RL" 0603 69.896,38.392 r0 bottom value=271
R19 "ERA-3ARW104V" 0603 72.239,45.493 r180 top value=100k
R20 "ERA-3ARW104V" 0603 72.239,47.434 r180 top value=100k
R21 "RMCF0603FT10K0" 0603 52.55,49.642 r90 bottom value=10.0k
R22 "RMCF0603FT10K0" 0603 72.239,41.587 r180 top value=10.0k
R23 "CRCW06031K00FKEA" 0603 96.28,41.322 r270 bottom value=1.00k
R24 "CRCW06031K00FKEA" 0603 100.163,41.322 r270 bottom value=1.00k
R25 "CRCW06031K00FKEA" 0603 104.046,41.322 r270 bottom value=1.00k
R26 "CRCW06031K00FKEA" 0603 99.761,52.949 r180 bottom value=1.00k
R27 "CRCW06031K00FKEA" 0603 92.397,41.322 r270 bottom value=1.00k
R28 "ERJ-PB3B6041V" FP-ERJ-PB3B6041V_0603-MFG 36.744,69.615 r180 top locked
R29 "RC0603FR-0710KL" 0603 39.997,67.54 r180 top locked value=10.0k
R30 "RC0603FR-0751R1L" 0603 22.579,59.328 r0 bottom locked value=51.1
R31 "RC0603FR-0751R1L" 0603 32.703,66.281 r270 bottom locked value=51.1
R32 "RC0603FR-0710KL" 0603 24.703,75.246 r0 top value=10.0k
R33 "RMCF0603ZT0R00" 0603 102.505,17.948 r180 top value=0
R34 "PMR03EZPJ000" 0603 102.505,9.75 r0 top value=0
R35 "CRCW120660R0KNEAIF" 1206 107.556,9.75 r270 top value=60
R36 "CRCW120660R0KNEAIF" 1206 107.556,15.449 r270 top value=60
R37 "PMR03EZPJ000" 0603 102.505,15.829 r0 top value=0
R38 "ERA-3ARW104V" 0603 25.128,52.244 r90 bottom value=100k
R39 "ERJ-PB3B6041V" FP-ERJ-PB3B6041V_0603-MFG 28.625,55 r180 bottom
R40 "PMR03EZPJ000" 0603 98.418,7.748 r270 top value=0
R41 "CRCW08050000Z0EAHP" 0805_HV 85.25,8.788 r0 bottom locked value=0
R42 "CRCW08050000Z0EAHP" 0805_HV 85.25,11.378 r0 bottom locked value=0
R43 "CRCW08050000Z0EAHP" 0805_HV 85.25,13.968 r0 bottom locked value=0
R44 "CRCW08050000Z0EAHP" 0805_HV 85.25,16.558 r0 bottom locked value=0
R45 "CRCW08050000Z0EAHP" 0805_HV 85.25,6.198 r0 bottom locked value=0
R46 "CRCW0603100RFKEAHP" 0603 48.97,21.894 r90 top locked value=100
R47 "CRCW0603100RFKEA" 0603 32.511,10.341 r90 bottom value=100
R48 "RCA12060000ZSEA" 1206 32.505,21.394 r90 top locked value=0
R49 "CRCW0603261KFKEA" 0603 22.859,14.459 r0 bottom value=261k
R50 "CRCW0603261KFKEA" 0603 26.581,2.64 r180 top locked value=261k
R51 "CRCW0603121KFKEA" 0603 29,9.786 r0 top value=121k
R52 "RCA12060000ZSEA" 1206 30.424,18.58 r0 bottom value=0
R53 "CRCW060312K1FKEA" 0603 30.186,2.64 r180 top locked value=12.1k
R54 "CRCW060364K9FKEA" 0603 50.827,17.446 r90 top locked value=64.9k
R55 "ERJ-PB3B6041V" FP-ERJ-PB3B6041V_0603-MFG 36.744,71.44 r180 top
R56 "RC0603FR-0710KL" 0603 36.744,75.246 r180 top value=10.0k
R57 "ERA-3ARW104V" 0603 61.573,12.561 r90 bottom locked value=100k
R58 "ERJ-PB3D9762V" FP-ERJ-PB3D9762V_0603-MFG 21.847,12.044 r90 bottom value=97.6k
R59 "CRCW06039K09FKEA" 0603 59.634,12.561 r270 bottom locked value=9.09k
R62 "CRCW06031K00FKEA" 0603 26.853,36.573 r180 top value=1.00k
R63 "RMCF0603FT10K0" 0603 30.533,38.45 r180 top locked value=10.0k
R64 "CRCW06031K00FKEA" 0603 63.754,9.75 r0 top value=1.00k
R65 "RMCF0603FT10K0" 0603 67.38,9.75 r180 top value=10.0k
R66 "RC0603FR-0710KL" 0603 16.982,48.844 r180 top value=10.0k
R67 "RC0603FR-0751R1L" 0603 35.194,58.948 r90 bottom value=51.1
R68 "ERJ-PB3B6041V" FP-ERJ-PB3B6041V_0603-MFG 16.982,43.663 r0 top
R69 "RC0603FR-0710KL" 0603 16.982,41.8 r180 top value=10.0k
R70 "RT0603BRD0718K4L" 0603 17.297,65.705 r0 top value=18.4k
R71 "RC0603FR-0710KL" 0603 17.147,69.509 r0 top value=10.0k
R72 "RT0603BRD0718K4L" 0603 13.463,65.671 r0 top value=18.4k
R73 "RC0603FR-0710KL" 0603 13.438,67.535 r0 top value=10.0k
R74 "ERJ-PB3B6041V" FP-ERJ-PB3B6041V_0603-MFG 28.932,52.26 r90 top
R75 "ERJ-PB3B6041V" FP-ERJ-PB3B6041V_0603-MFG 16.982,45.321 r180 top
R76 "RC0603FR-0710KL" 0603 27.069,52.26 r90 top value=10.0k
R77 "ERJ-PB3B6041V" FP-ERJ-PB3B6041V_0603-MFG 30.591,52.26 r90 top
R78 "RC0603FR-0710KL" 0603 32.455,52.26 r90 top value=10.0k
R79 "ERJ-PB3B6041V" FP-ERJ-PB3B6041V_0603-MFG 31.287,52.26 r90 bottom
R80 "ERJ-PB3B6041V" FP-ERJ-PB3B6041V_0603-MFG 29.25,47.583 r0 top
R81 "RC0603FR-0751R1L" 0603 25.053,61.375 r0 bottom value=51.1
R82 "RC0603FR-0710KL" 0603 29.423,52.26 r90 bottom value=10.0k
R83 "ERJ-PB3B6041V" FP-ERJ-PB3B6041V_0603-MFG 29.25,45.925 r180 top
R84 "RC0603FR-0710KL" 0603 29.25,44.061 r180 top value=10.0k
R85 "ERJ-PB3B6041V" FP-ERJ-PB3B6041V_0603-MFG 32.945,52.26 r90 bottom
R86 "RC0603FR-0710KL" 0603 34.809,52.26 r90 bottom value=10.0k
R87 "RC0603FR-0710KL" 0603 31.432,62.557 r180 bottom value=10.0k
R88 "CRCW06031K00FKEA" 0603 66.505,9.75 r180 bottom value=1.00k
T1 "ZA9672-BE" FP-ZA9672-BE_SMD8-MFG 38.964,11.719 r0 top locked
U1 "REF3133AQDBZRQ1" DBZ0003A_N 38.294,49.589 r270 top
U2 "DRV3256EPAPRQ1" PAP0064N-MFG 60,43.25 r270 top
U3 "TLV9064IPWR" PW0014A_N 30.749,70.77 r0 top
U4 "TLV9064IPWR" PW0014A_N 23.205,45.294 r0 top locked
U5 "TXB0106PWR" PW0016A_N 96.28,47.595 r270 bottom
U6 "TCAN1044DDFRQ1" DDF0008A-MFG 95.151,12.802 r0 top
U7 "ISO7731DWR" DW0016B_HV 84.941,12.013 r0 top
U8 "TPS7B6950QDBVRQ1" DBV0005A_N 94.942,3.059 r0 top
U9 "LM25184QNGURQ1" NGU0008C 27.504,6.246 r270 top locked
U10 "LMR38010SQDDARQ1" DDA0008E-MFG 55.015,14.799 r270 top locked
U11 "LMR33620AQ5RNXRQ1" RNX0012B 49.852,8.121 r270 top
U12 "TPS7B4255QDBVRQ1" DBV0005A-MFG 71.282,19.735 r90 top locked
U13 "TPS7B4255QDBVRQ1" DBV0005A-MFG 18.127,36.573 r180 top
U14 "TPS7A21XXPQWDRBRQ1" DRB0008K-MFG 73.481,5.799 r180 top locked
ZZ1 "This Assembly Note is for PCB labels only" AssemblyNoteLabel 4.8,99.1 r0 top
ZZ2 "These assemblies are ESD sensitive, ESD precautions shall be observed." AssemblyNote 4.786,97.25 r0 top
ZZ3 "These assemblies must be clean and free from flux and all contaminants. Use of no clean flux is not acceptable." AssemblyNote 4.78,95.25 r0 top
ZZ4 "These assemblies must comply with workmanship standards IPC-A-610 Class 2, unless otherwise specified." AssemblyNote 4.786,93.25 r0 top

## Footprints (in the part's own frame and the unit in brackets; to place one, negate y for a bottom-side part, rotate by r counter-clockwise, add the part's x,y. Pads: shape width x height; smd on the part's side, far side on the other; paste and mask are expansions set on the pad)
0402 [mm] "0402 from SM-752 data"
  rect 0.8x0.6 smd: 1(-0.6,0) 2(0.6,0)
  silkscreen extent -1.22,-0.52 1.22,0.52, body extent -0.55,-0.3 0.55,0.3, height 0.6
0603 [mm] "0603 from SM-752 data"
  rect 1x0.95 smd: 1(-0.8,0) 2(0.8,0)
  silkscreen extent -1.52,-0.69 1.52,0.69, body extent -0.87,-0.47 0.87,0.47, height 1
0603_HV [mil] "Ernesto recommended land pattern.  26 mil between pads."
  rect 30x30 smd: 1(-28,0) 2(28,0)
  silkscreen extent -52,-24 52,24, body extent -34,-19 34,19, height 39
0805_HV [mil] "0805 with 30mil clearance between pads"
  rect 50x63 smd: 1(-40,0) 2(40,0)
  silkscreen extent -74,-40 74,40, body extent -43,-29 43,29, height 57
1206 [mm] "1206 from SM-752 data"
  rect 1.3x1.85 smd: 1(-1.45,0) 2(1.45,0)
  silkscreen extent -2.4,-1.21 2.4,1.21, body extent -1.7,-0.9 1.7,0.9, height 1.35
1206_180 [mm] "1206_180"
  rect 1.1x1.6 smd: 1(-1.7,0) 2(1.7,0)
  silkscreen extent -0.9,-1 0.9,1, body extent -1.75,-0.95 1.75,0.95, height 1.8
1206_190 [mm] "1206_190"
  rect 1.1x1.6 smd: 1(-1.7,0) 2(1.7,0)
  silkscreen extent -0.9,-1 0.9,1, body extent -1.75,-0.95 1.75,0.95, height 1.9
1206_190M [mm] "1206_190"
  rect 1.5x1.95 smd: 1(-1.55,0) 2(1.55,0)
  silkscreen extent -2.76,-1.44 2.76,1.44, body extent -1.75,-0.95 1.75,0.95, height 1.9
1210_270 [mm] "1210"
  rect 1.3x2.7 smd: 1(-1.45,0) 2(1.45,0)
  silkscreen extent -2.32,-1.57 2.32,1.57, body extent -1.7,-1.35 1.7,1.35, height 2.7
1210_280 [mm] "SMD, 2-Leads, Body 3.6x2.8mm, Height 2.8mm"
  rect 1.1x2.2 smd: 1(-1.65,0) 2(1.65,0)
  silkscreen extent -0.84,-1.4 0.84,1.4, body extent -1.8,-1.4 1.8,1.4, height 2.8
2220_250 [mm] "2220"
  rect 1.6x5.3 smd: 1(-2.6,0) 2(2.6,0)
  silkscreen extent -3.69,-2.94 3.69,2.94, body extent -2.95,-2.62 2.95,2.62, height 2.5
ACT45B_NoSilk [mm] "SMD, 4-Leads, Body 4.7 x 3.7 mm"
  rect 1.35x0.9 smd: 1(-2.275,1.25) 2(-2.275,-1.25) 3(2.275,-1.25) 4(2.275,1.25)
  body extent -2.35,-1.7 2.35,1.7, height 3
AssemblyNote [mm] "Assembly Note"
AssemblyNoteLabel [mm] "Assembly Note for PCB Labels"
CE_Mark_5mm [mm] "Minimum text height for CE Mark"
  silkscreen extent -3.5,-2.5 3.5,2.5
controlCARD-120HSEC [mm] "Pads are not numbered according to Samtec datasheet."
  rect 0.5x2.724 smd: 1(-23.357,-1.678) 2(-23.357,1.722) 3(-22.557,-1.678) 4(-22.557,1.722) 5(-21.757,-1.678) 6(-21.757,1.722) 7(-20.957,-1.678) 8(-20.957,1.722) 9(-20.157,-1.678) 10(-20.157,1.722) 11(-19.357,-1.678) 12(-19.357,1.722) 13(-18.557,-1.678) 14(-18.557,1.722) 15(-17.757,-1.678) 16(-17.757,1.722) 17(-16.957,-1.678) 18(-16.957,1.722) 19(-16.157,-1.678) 20(-16.157,1.722) 21(-15.357,-1.678) 22(-15.357,1.722) 23(-14.557,-1.678) 24(-14.557,1.722) 25(-13.757,-1.678) 26(-13.757,1.722) 27(-12.957,-1.678) 28(-12.957,1.722) 29(-12.157,-1.678) 30(-12.157,1.722) 31(-11.357,-1.678) 32(-11.357,1.722) 33(-10.557,-1.678) 34(-10.557,1.722) 35(-9.757,-1.678) 36(-9.757,1.722) 37(-8.957,-1.678) 38(-8.957,1.722) 39(-8.157,-1.678) 40(-8.157,1.722) 41(-7.357,-1.678) 42(-7.357,1.722) 43(-6.557,-1.678) 44(-6.557,1.722) 45(-5.757,-1.678) 46(-5.757,1.722) 47(-4.957,-1.678) 48(-4.957,1.722) 49(-4.157,-1.678) 50(-4.157,1.722) 51(-3.357,-1.678) 52(-3.357,1.722) 53(-2.557,-1.678) 54(-2.557,1.722) 55(-1.757,-1.678) 56(-1.757,1.722) 57(2.243,-1.678) 58(2.243,1.722) 59(3.043,-1.678) 60(3.043,1.722) 61(3.843,-1.678) 62(3.843,1.722) 63(4.643,-1.678) 64(4.643,1.722) 65(5.443,-1.678) 66(5.443,1.722) 67(6.243,-1.678) 68(6.243,1.722) 69(7.043,-1.678) 70(7.043,1.722) 71(7.843,-1.678) 72(7.843,1.722) 73(8.643,-1.678) 74(8.643,1.722) 75(9.443,-1.678) 76(9.443,1.722) 77(10.243,-1.678) 78(10.243,1.722) 79(11.043,-1.678) 80(11.043,1.722) 81(11.843,-1.678) 82(11.843,1.722) 83(12.643,-1.678) 84(12.643,1.722) 85(13.443,-1.678) 86(13.443,1.722) 87(14.243,-1.678) 88(14.243,1.722) 89(15.043,-1.678) 90(15.043,1.722) 91(15.843,-1.678) 92(15.843,1.722) 93(16.643,-1.678) 94(16.643,1.722) 95(17.443,-1.678) 96(17.443,1.722) 97(18.243,-1.678) 98(18.243,1.722) 99(19.043,-1.678) 100(19.043,1.722) 101(19.843,-1.678) 102(19.843,1.722) 103(20.643,-1.678) 104(20.643,1.722) 105(21.443,-1.678) 106(21.443,1.722) 107(22.243,-1.678) 108(22.243,1.722) 109(23.043,-1.678) 110(23.043,1.722) 111(23.843,-1.678) 112(23.843,1.722) 113(24.643,-1.678) 114(24.643,1.722) 115(25.443,-1.678) 116(25.443,1.722) 117(26.243,-1.678) 118(26.243,1.722) 119(27.043,-1.678) 120(27.043,1.722)
  round 0.025 hole 1.27 unplated mask+0.876: 181(-24.857,0.022) 182(28.543,1.522)
  round 1.348 hole 0.84: 185(-27.207,0.022) 186(30.893,0.022)
  silkscreen extent -32.11,-3.86 35.8,3.9, body extent -31.75,-3.48 35.3,3.52, height 12.35
controlCARD-180HSEC-60pinAddon [mm] "Pads are not numbered according to datasheet."
  round 0.025 hole 1.27 unplated mask+0.876: 61(-13.1,0) 62(13.1,1.5)
  rect 0.5x2.724 smd: 121(-11.6,-1.7) 122(-11.6,1.7) 123(-10.8,-1.7) 124(-10.8,1.7) 125(-10,-1.7) 126(-10,1.7) 127(-9.2,-1.7) 128(-9.2,1.7) 129(-8.4,-1.7) 130(-8.4,1.7) 131(-7.6,-1.7) 132(-7.6,1.7) 133(-6.8,-1.7) 134(-6.8,1.7) 135(-6,-1.7) 136(-6,1.7) 137(-5.2,-1.7) 138(-5.2,1.7) 139(-4.4,-1.7) 140(-4.4,1.7) 141(-3.6,-1.7) 142(-3.6,1.7) 143(-2.8,-1.7) 144(-2.8,1.7) 145(-2,-1.7) 146(-2,1.7) 147(-1.2,-1.7) 148(-1.2,1.7) 149(-0.4,-1.7) 150(-0.4,1.7) 151(0.4,-1.7) 152(0.4,1.7) 153(1.2,-1.7) 154(1.2,1.7) 155(2,-1.7) 156(2,1.7) 157(2.8,-1.7) 158(2.8,1.7) 159(3.6,-1.7) 160(3.6,1.7) 161(4.4,-1.7) 162(4.4,1.7) 163(5.2,-1.7) 164(5.2,1.7) 165(6,-1.7) 166(6,1.7) 167(6.8,-1.7) 168(6.8,1.7) 169(7.6,-1.7) 170(7.6,1.7) 171(8.4,-1.7) 172(8.4,1.7) 173(9.2,-1.7) 174(9.2,1.7) 175(10,-1.7) 176(10,1.7) 177(10.8,-1.7) 178(10.8,1.7) 179(11.6,-1.7) 180(11.6,1.7)
  silkscreen extent -14.68,-3.88 14.68,3.88, body extent -14.3,-3.5 14.3,3.5, height 7.95
DBV0005A-MFG [mm]
  rrect17% 1.1x0.6 smd paste+0 mask+0: 1(-1.3,0.95) 2(-1.3,0) 3(-1.3,-0.95) 4(1.3,-0.95) 5(1.3,0.95)
  silkscreen extent -2.57,-1.53 0.87,1.53, body extent -1.95,-1.78 1.95,1.78, height 0.25
DBV0005A_N [mm] "SOT23, 5-Leads, Body 2.9x1.6mm, Pitch 0.95mm, Lead Span 2.8mm, IPC Medium Density"
  rrect17% 1x0.6 smd: 1(-1.375,0.95) 2(-1.375,0) 3(-1.375,-0.95) 4(1.375,-0.95) 5(1.375,0.95)
  silkscreen extent -1.63,-1.55 0.38,1.55, body extent -1.42,-1.46 1.42,1.46, height 1.09
DBZ0003A_N [mm] "SOT23, 3-Leads, Body 2.9x1.3mm, Pitch 0.95mm, Lead Span 2.4mm, IPC Medium Density"
  rrect17% 1x0.6 smd: 1(-1.2,0.95) 2(-1.2,-0.95) 3(1.2,0)
  silkscreen extent 0.2,-1.5 0.7,1.5, body extent -1.26,-1.46 1.26,1.46, height 0.98
DDA0008E-MFG [mm]
  rrect20% 2.2x0.5 smd paste-1000 mask+0: 1(-2.875,1.905) 2(-2.875,0.635) 3(-2.875,-0.635) 4(-2.875,-1.905) 5(2.875,-1.905) 6(2.875,-0.635) 7(2.875,0.635) 8(2.875,1.905)
  rrect3% 2.95x4.9 smd paste-1000 mask-1000: 9(0,0)
  silkscreen extent -4.67,-2.83 2,2.83, body extent -4.08,-2.68 4.08,2.68, height 0.25
DDF0008A-MFG [mm]
  rrect22% 1.05x0.45 smd paste+0 mask+0: 1(-1.3,0.975) 2(-1.3,0.325) 3(-1.3,-0.325) 4(-1.3,-0.975) 5(1.3,-0.975) 6(1.3,-0.325) 7(1.3,0.325) 8(1.3,0.975)
  silkscreen extent -2.5,-1.48 0.4,1.48, body extent -1.92,-1.73 1.92,1.73, height 0.25
DRB0008K-MFG [mm]
  rrect33% 0.6x0.3 smd paste+0 mask+0: 1(-1.4,0.975) 2(-1.4,0.325) 3(-1.4,-0.325) 4(-1.4,-0.975) 5(1.4,-0.975) 6(1.4,-0.325) 7(1.4,0.325) 8(1.4,0.975)
  rrect6% 1.6x2.4 smd paste-1000 mask+0: 9(0,0)
  silkscreen extent -2.4,-1.55 1.55,1.55, body extent -1.8,-1.65 1.8,1.65, height 0.25
DW0016B_HV [mm] "SOIC-16, HV/isolation option"
  rrect17% 1.65x0.6 smd: 1(-4.875,4.445) 2(-4.875,3.175) 3(-4.875,1.905) 4(-4.875,0.635) 5(-4.875,-0.635) 6(-4.875,-1.905) 7(-4.875,-3.175) 8(-4.875,-4.445) 9(4.875,-4.445) 10(4.875,-3.175) 11(4.875,-1.905) 12(4.875,-0.635) 13(4.875,0.635) 14(4.875,1.905) 15(4.875,3.175) 16(4.875,4.445)
  body extent -5.17,-5.15 5.17,5.15, height 2.59
FCC_disclaimer [mm]
Fiducial10-20 [mm]
  round 1 smd mask+0.5: 1(0,0)
  Top Layer keep-out circle w1.178: c0,0 r0.5
FP-ERJ-PB3B6041V_0603-MFG [mm]
  rrect15% 0.65x0.9 smd paste+0 mask+0: 1(-0.725,0) 2(0.725,0)
  silkscreen extent -0.03,-0.48 0.02,0.48, body extent -1.15,-0.58 1.15,0.58, height 0.25
FP-ERJ-PB3D9762V_0603-MFG [mm]
  rrect15% 0.65x0.9 smd paste+0 mask+0: 1(-0.725,0) 2(0.725,0)
  silkscreen extent 0,-0.48 0,0.48, body extent -0.8,-0.4 0.8,0.4, height 0.55
FP-ZA9672-BE_SMD8-MFG [mm]
  rrect8% 2.03x1.27 smd paste+0 mask+0: 1(-5.715,3.75) 2(-5.715,1.25) 3(-5.715,-1.25) 4(-5.715,-3.75) 5(5.715,-3.75) 6(5.715,-1.25) 7(5.715,1.25) 8(5.715,3.75)
  silkscreen extent -7.5,-5.46 6.61,5.46, body extent -6.83,-5.56 6.83,5.56, height 0.25
Label_650x200 [mil] "Thermal Transfer Label"
  round 1 on Mech13: 0(0,0)
  silkscreen extent -325,-100 325,100, body extent -325,-100 325,100, height 1
Mill-Max_801-41-003-10-001000 [mm] "Receptacle, 2.54mm, 3x1, TH"
  rrect50% 1.35x1.35 hole 0.9: 1(-2.54,0)
  round 1.35 hole 0.9: 2(0,0) 3(2.54,0)
  silkscreen extent -3.81,-1.75 3.81,1.27, body extent -3.81,-1.27 3.81,1.27, height 7.01
Molex_0734151471 [mm] "MMCX JACK, Gold, TH"
  round 1.35 hole 0.84: 1(0,0) 2(-1.27,1.27) 3(1.27,1.27) 4(1.27,-1.27) 5(-1.27,-1.27)
  silkscreen extent -1.8,-1.8 1.8,1.8, body extent -1.76,-1.76 1.76,1.76, height 4.42
NGU0008C [mm] "SON, 8-Leads, Body 4x4mm, Pitch 0.8mm"
  rrect33% 0.6x0.3 smd: 1(-1.9,1.2) 2(-1.9,0.4) 3(-1.9,-0.4) 4(-1.9,-1.2) 5(1.9,-1.2) 6(1.9,-0.4) 7(1.9,0.4) 8(1.9,1.2)
  rrect8% 1.75x1.31 on Top Paste: 9(0,0.755) 9(0,-0.755)
  rrect5% 1.98x3 smd paste-1.5: 9(0,0)
  silkscreen extent -2.15,-2.15 2.15,2.15, body extent -2,-2 2,2, height 0.77
NORCOMP_190-009-263R001 [mil] "Norcomp"
  rect 32x146 smd: 1(-218,-84) 2(-109,-84) 3(0,-84) 4(109,-84) 5(218,-84) 6(-163.5,-84) 7(-54.5,-84) 8(54.5,-84) 9(163.5,-84)
  round 180 hole 120: 10(-492,-110) 11(492,-110)
  round 40 hole 59 unplated: MH(-313,-110) MH(313,-110)
  silkscreen extent -620,-160 630,-95, body extent -593,-138 592,280, height 425
PA4342_2 [mm] "SMD, 2-Leads, Body 11.5x10.3mm"
  rect 3.5x4.1 smd: 1(0,4.75) 2(0,-4.75)
  silkscreen extent -5.15,-5.75 5.15,5.75, body extent -5.15,-5.75 5.15,5.75, height 4
PAP0064N-MFG [mm]
  rrect33% 1.5x0.3 smd paste+0 mask+0: 1(-5.7,3.75) 2(-5.7,3.25) 3(-5.7,2.75) 4(-5.7,2.25) 5(-5.7,1.75) 6(-5.7,1.25) 7(-5.7,0.75) 8(-5.7,0.25) 9(-5.7,-0.25) 10(-5.7,-0.75) 11(-5.7,-1.25) 12(-5.7,-1.75) 13(-5.7,-2.25) 14(-5.7,-2.75) 15(-5.7,-3.25) 16(-5.7,-3.75) 33(5.7,-3.75) 34(5.7,-3.25) 35(5.7,-2.75) 36(5.7,-2.25) 37(5.7,-1.75) 38(5.7,-1.25) 39(5.7,-0.75) 40(5.7,-0.25) 41(5.7,0.25) 42(5.7,0.75) 43(5.7,1.25) 44(5.7,1.75) 45(5.7,2.25) 46(5.7,2.75) 47(5.7,3.25) 48(5.7,3.75)
  rrect33% 0.3x1.5 smd paste+0 mask+0: 17(-3.75,-5.7) 18(-3.25,-5.7) 19(-2.75,-5.7) 20(-2.25,-5.7) 21(-1.75,-5.7) 22(-1.25,-5.7) 23(-0.75,-5.7) 24(-0.25,-5.7) 25(0.25,-5.7) 26(0.75,-5.7) 27(1.25,-5.7) 28(1.75,-5.7) 29(2.25,-5.7) 30(2.75,-5.7) 31(3.25,-5.7) 32(3.75,-5.7) 49(3.75,5.7) 50(3.25,5.7) 51(2.75,5.7) 52(2.25,5.7) 53(1.75,5.7) 54(1.25,5.7) 55(0.75,5.7) 56(0.25,5.7) 57(-0.25,5.7) 58(-0.75,5.7) 59(-1.25,5.7) 60(-1.75,5.7) 61(-2.25,5.7) 62(-2.75,5.7) 63(-3.25,5.7) 64(-3.75,5.7)
  rrect1% 8x8 smd paste-1000 mask-1000: 65(0,0)
  silkscreen extent -7.15,-5.1 5.1,5.1, body extent -6.01,-6.01 6.01,6.01, height 1.2
PowerDI323 [mm] "Diodes Inc."
  rect 2x1.1 smd: 1(-0.65,0)
  rect 0.8x0.8 smd: 2(1.25,0)
  silkscreen extent -2.3,-0.89 1.1,0.89, body extent -1.1,-0.65 1.5,0.65, height 0.7
PW0014A_N [mm] "TSOP, 14-Leads, Body 5x4.4mm, Pitch 0.65mm, IPC Medium Density"
  oval 1.4x0.45 smd: 1(-2.95,1.95) 2(-2.95,1.3) 3(-2.95,0.65) 4(-2.95,0) 5(-2.95,-0.65) 6(-2.95,-1.3) 7(-2.95,-1.95) 8(2.95,-1.95) 9(2.95,-1.3) 10(2.95,-0.65) 11(2.95,0) 12(2.95,0.65) 13(2.95,1.3) 14(2.95,1.95)
  silkscreen extent -3.4,-2.55 1.85,2.55, body extent -3.21,-2.5 3.21,2.5, height 1
PW0016A_N [mm] "TSOP, 16-Leads, Body 5x4.4mm, Pitch 0.65mm, IPC Medium Density"
  oval 1.4x0.45 smd: 1(-2.95,2.275) 2(-2.95,1.625) 3(-2.95,0.975) 4(-2.95,0.325) 5(-2.95,-0.325) 6(-2.95,-0.975) 7(-2.95,-1.625) 8(-2.95,-2.275) 9(2.95,-2.275) 10(2.95,-1.625) 11(2.95,-0.975) 12(2.95,-0.325) 13(2.95,0.325) 14(2.95,0.975) 15(2.95,1.625) 16(2.95,2.275)
  silkscreen extent -3.5,-2.55 1.85,2.75, body extent -3.21,-2.5 3.21,2.5, height 1
RNX0012B [mm] "VQFN-HR-12"
  rrect40% 0.6x0.25 smd: 1(-0.9,1.125) 2(-0.9,0.475) 3(-0.9,-0.175) 4(-0.9,-0.675) 8(0.9,-0.675) 9(0.9,-0.175) 10(0.9,0.475) 11(0.9,1.125)
  rrect40% 0.25x0.6 smd: 5(-0.5,-1.4) 6(0,-1.4) 7(0.5,-1.4)
  rrect40% 0.25x1.825 smd paste-0.175: 12(0,0.788)
  body extent -1,-1.5 1,1.5, height 1
Samtec_TSS-108-04-x-D-RA [mm] "Header (Shrouded), 2.54mm, 8x2, R/A, TH"
  rect 1.55x1.55 hole 1.02: 1(-1.27,8.89)
  round 1.55 hole 1.02: 2(1.27,8.89) 3(-1.27,6.35) 4(1.27,6.35) 5(-1.27,3.81) 6(1.27,3.81) 7(-1.27,1.27) 8(1.27,1.27) 9(-1.27,-1.27) 10(1.27,-1.27) 11(-1.27,-3.81) 12(1.27,-3.81) 13(-1.27,-6.35) 14(1.27,-6.35) 15(-1.27,-8.89) 16(1.27,-8.89)
  silkscreen extent -1.52,-12.06 11.05,12.07, body extent -1.59,-12.07 11.05,12.06, height 9.3
Samtec_TSW-105-08-x-D [mm] "Header, 2.54mm, 5x2, TH"
  rrect50% 1.53x1.53 hole 1.02: 1(-1.27,5.08)
  round 1.53 hole 1.02: 2(1.27,5.08) 3(-1.27,2.54) 4(1.27,2.54) 5(-1.27,0) 6(1.27,0) 7(-1.27,-2.54) 8(1.27,-2.54) 9(-1.27,-5.08) 10(1.27,-5.08)
  body extent -2.54,-6.35 2.54,6.35, height 8.38
SMA [mm] "Molded Diode, 2-Leads, Body 4.3x2.6mm, IPC Medium Density, based on OnSemi component dimensions and land pattern"
  rect 2x2 smd: 1(-2,0) 2(2,0)
  silkscreen extent -3.66,-1.57 2.79,1.57, body extent -2.6,-1.3 2.6,1.3, height 2.42
SMC_265 [mm] "SMD, 2-Leads, Body 7.15x6.25mm"
  rect 2.6x3.2 smd: 1(-3.6,0) 2(3.6,0)
  silkscreen extent -5.6,-3.22 5.3,3.23, body extent -4.07,-3.13 4.07,3.13, height 2.65
SOD-123W [mm] "NXP recommended land pattern"
  rect 1.2x1.2 smd paste-0.05: 1(-1.4,0) 2(1.4,0)
  silkscreen extent -2.64,-1.14 1.68,1.14, body extent -1.85,-0.95 1.85,0.95, height 1.1
SOT-23 [mm] "SOT23, 3-Leads, Body 2.9x1.3mm, Pitch 0.95mm, Lead Span 2.5mm, IPC Medium Density"
  rrect50% 1x0.6 smd: 1(-1.2,0.95) 2(-1.2,-0.95) 3(1.2,0)
  silkscreen extent -1.63,-1.5 0.7,1.5, body extent -1.16,-1.45 1.21,1.45, height 1
SOT-323 [mm] "Diodes Inc recommended land pattern.  2016-02-24"
  rrect21% 0.6x0.47 smd: 1(-0.95,0.65) 2(-0.95,-0.65) 3(0.95,0)
  silkscreen extent -1.14,-1.22 0.77,1.22, body extent -1.13,-1.13 1.12,1.12, height 1.13
SRN6045TA [mm] "SMD, 2-Leads, Body 6x6mm"
  rect 2.35x5.1 smd: 1(-2.075,0) 2(2.075,0)
  silkscreen extent -2.49,-3.01 2.5,2.98, body extent -3,-3 3,2.99, height 4
TI_Stacked_Overlay_Small [mm]
  silkscreen extent -10.63,-2.49 10.63,2.49
WEEE_Minimum [mm] "WEEElie bin"
  silkscreen extent -2.42,-4.38 2.52,2.65
WL-SMCW_GREEN [mm] "WURTH"
  rect 0.8x0.8 smd: 1(-0.8,0) 2(0.8,0)
  silkscreen extent -1.9,-0.8 1.2,0.8, body extent -0.85,-0.45 0.85,0.45, height 0.8
WL-SMCW_RED [mm] "WURTH"
  rect 0.8x0.8 smd: 1(-0.8,0) 2(0.8,0)
  silkscreen extent -1.9,-0.8 1.2,0.8, body extent -0.85,-0.45 0.85,0.45, height 0.8

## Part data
C1 C2 C15 C16: library part CMP-0007078-4, "CAP, CERM, 0.1 uF, 50 V, +/- 10%, X7R, AEC-Q200 Grade 1, 0603", Cap_Case=0603, Manufacturer=TDK, Supplier Part Number 1=445-5666-1-ND, TempCo=X7R, Tolerance_%=10%, Value1="0.0296 ohm", Value2=50V, ValueDisplayed=0.1uF
C3 C58: library part CMP-0009414-2, "CAP, CERM, 4.7 uF, 100 V, +/- 20%, X7R, AEC-Q200 Grade 1,", Cap_Case=2220, Manufacturer=TDK, Supplier Part Number 1=445-13141-1-ND, TempCo=X7R, Tolerance_%=20%, Value1=Unknown, Value2=100V, ValueDisplayed=4.7uF
C4: library part CMP-0007098-4, "CAP, CERM, 0.47 uF, 50 V, +/- 20%, X7R, AEC-Q200 Grade 1, 0603", Cap_Case=0603, Manufacturer=TDK, Supplier Part Number 1=445-172476-1-ND, TempCo=X7R, Tolerance_%=20%, Value1=Unknown, Value2=50V, ValueDisplayed=0.47uF
C5 C6 C8 C9 C10 C11 C87 C92: library part CMP-0085645-1, "CAP, CERM, 4.7 µF, 25 V,+/- 10%, X6S, AEC-Q200 Grade 2, 0603", Cap_Case=0603, Manufacturer=MuRata, TempCo=X6S, Tolerance_%=10%, Value2=25V, ValueDisplayed=4.7µF
C7: library part CMP-0008781-2, "CAP, CERM, 0.47 uF, 100 V, +/- 10%, X7R, AEC-Q200 Grade 1, 1206", Cap_Case=1206_180, Manufacturer=TDK, Supplier Part Number 1=445-5844-1-ND, TempCo=X7R, Tolerance_%=10%, Value1="0.007558 ohm", Value2=100V, ValueDisplayed=0.47uF
C12: library part CMP-0006326-2, "CAP, CERM, 0.1 uF, 50 V, +/- 20%, X7R, AEC-Q200 Grade 1, 0402", Cap_Case=0402, Manufacturer=TDK, Supplier Part Number 1=445-12271-1-ND, TempCo=X7R, Tolerance_%=20%, Value1=Unknown, Value2=50V, ValueDisplayed=0.1uF
C13 C32 C34 C76 C88 C93: library part CMP-0079911-1, "CAP, CERM, 0.1 µF, 50 V,+/- 10%, X8R, AEC-Q200 Grade 0, 0603", Cap_Case=0603, Manufacturer=TDK, Supplier Part Number 1=445-173697-1-ND, TempCo=X8R, Tolerance_%=10%, Value2=50V, ValueDisplayed=0.1µF
C14 C33 C35: library part CMP-0085950-1, "CAP, CERM, 10 µF, 50 V,+/- 10%, X7R, AEC-Q200 Grade 1, 1206", Cap_Case=1206, Manufacturer=TDK, TempCo=X7R, Tolerance_%=10%, Value2=50V, ValueDisplayed=10µF
C17 C18 C19 C53: library part CMP-0007173-4, "CAP, CERM, 1000 pF, 50 V, +/- 5%, C0G/NP0, 0603", Cap_Case=0603, Manufacturer=MuRata, Supplier Part Number 1=490-1451-1-ND, TempCo=C0G/NP0, Tolerance_%=5%, Value1=Unknown, Value2=50V, ValueDisplayed=1000pF
C20 C54 C56 C78 C80 C82 C83 C84 C85 C86 C89 C91 C94 C95: library part CMP-0007127-4, "CAP, CERM, 470 pF, 50 V, +/- 5%, C0G/NP0, AEC-Q200 Grade 1, 0603", Cap_Case=0603, Manufacturer=MuRata, Supplier Part Number 1=490-4965-1-ND, TempCo=C0G/NP0, Tolerance_%=5%, Value1=Unknown, Value2=50V, ValueDisplayed=470pF
C21 C22 C55 C77 C79 C81 C90: library part CMP-0007221-4, "CAP, CERM, 470 pF, 50 V, +/- 5%, C0G/NP0, 0603", Cap_Case=0603, Manufacturer=MuRata, Supplier Part Number 1=490-1443-1-ND, TempCo=C0G/NP0, Tolerance_%=5%, Value1=Unknown, Value2=50V, ValueDisplayed=470pF
C23 C25 C27: library part CMP-0007965-2, "CAP, CERM, 10 uF, 16 V, +/- 10%, X7S, AEC-Q200 Grade 1, 0805", Cap_Case=0805, Manufacturer=TDK, Supplier Part Number 1=445-16110-1-ND, TempCo=X7S, Tolerance_%=10%, Value1=Unknown, Value2=16V, ValueDisplayed=10uF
